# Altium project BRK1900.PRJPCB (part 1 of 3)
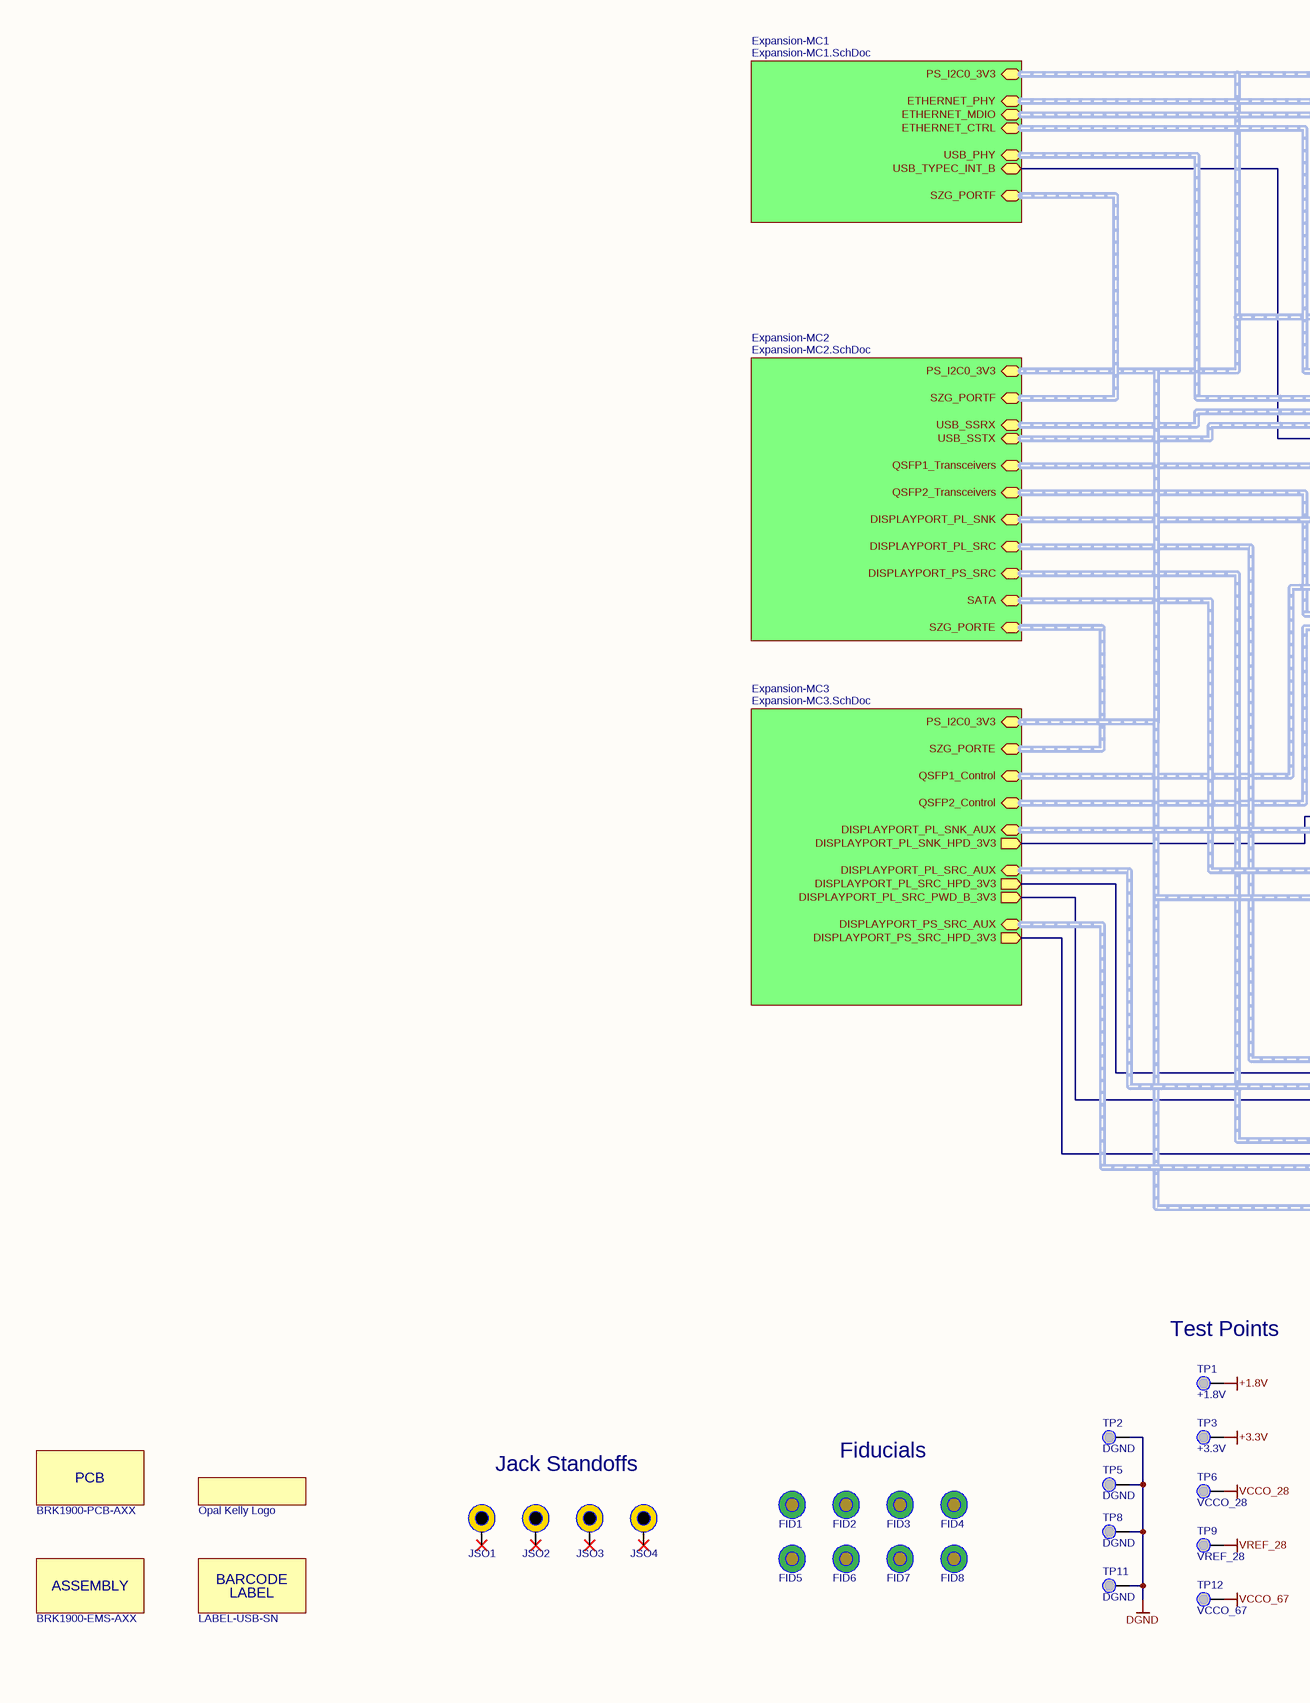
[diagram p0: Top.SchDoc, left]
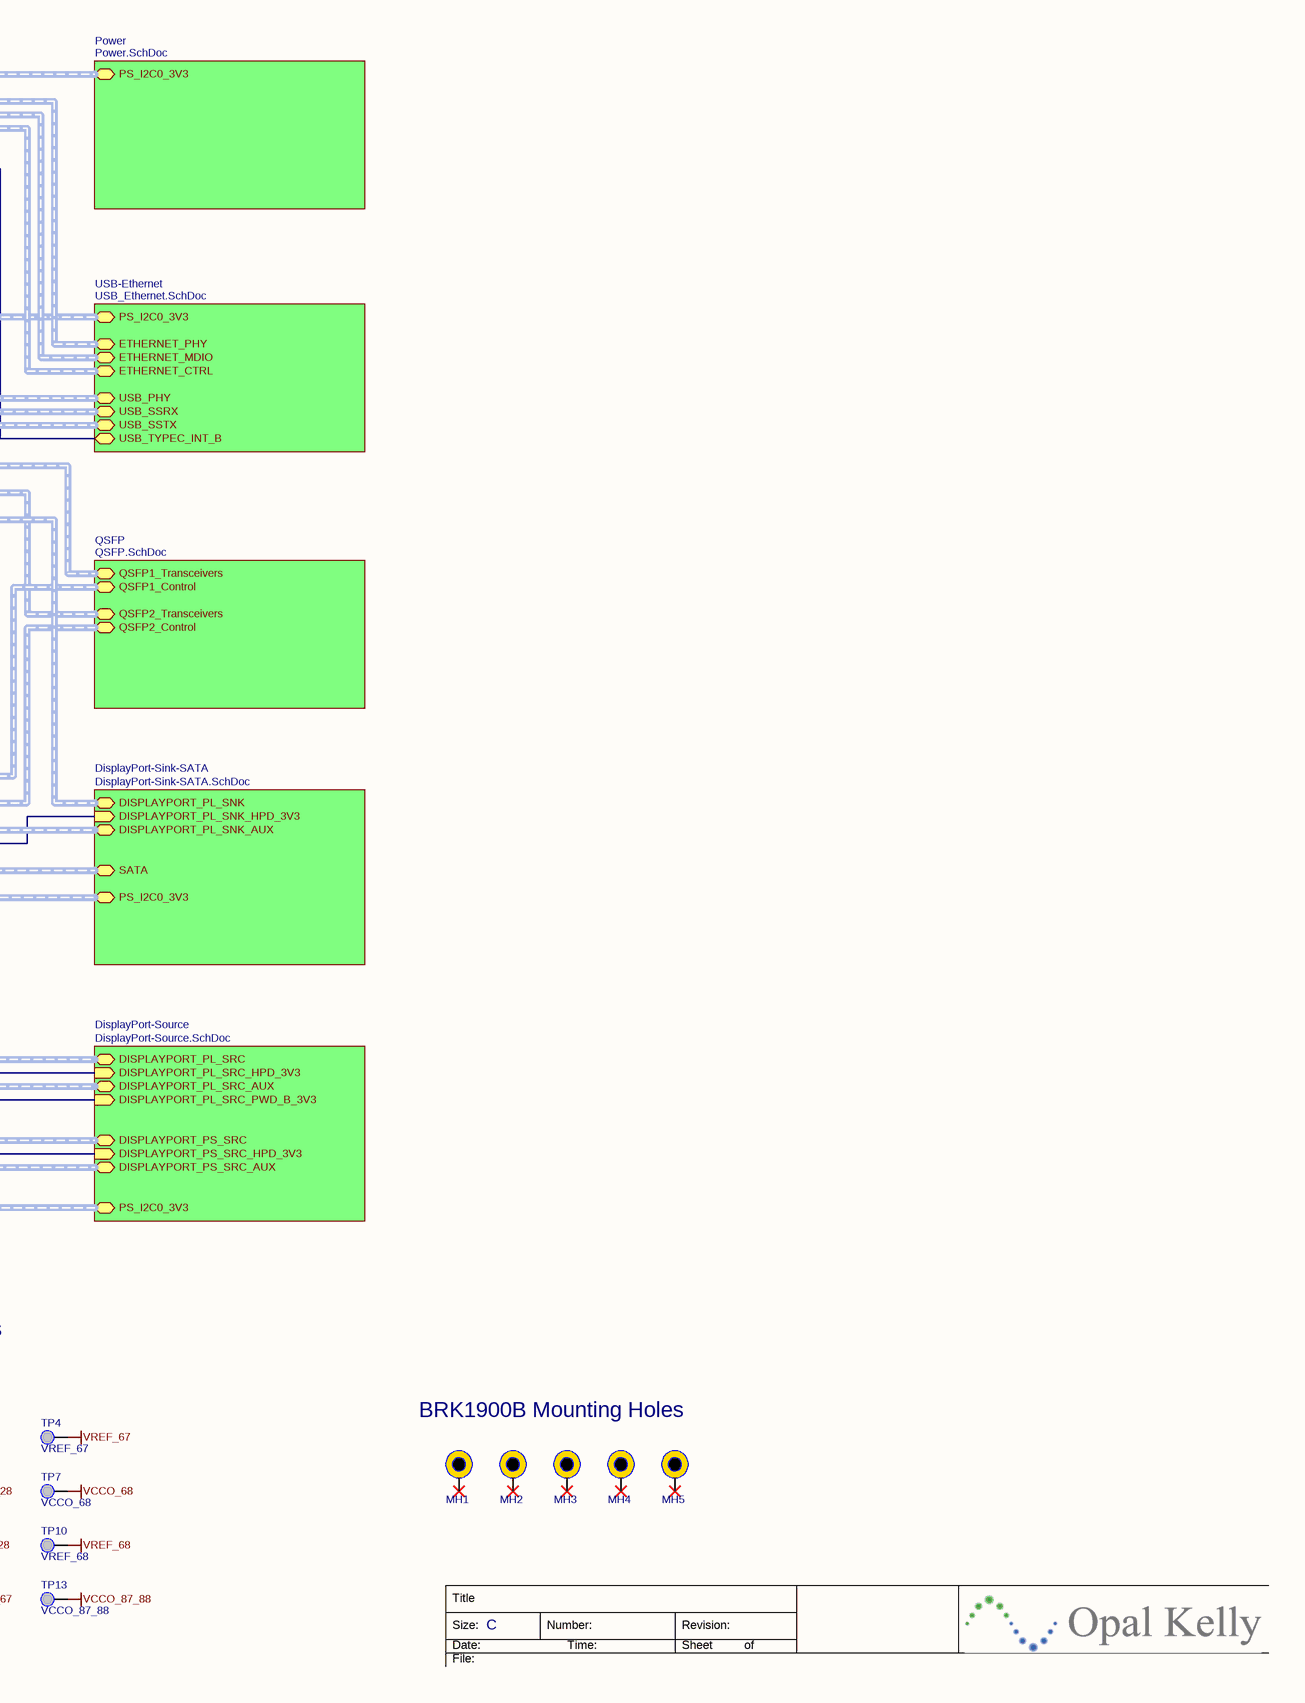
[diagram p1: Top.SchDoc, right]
BOM_Revision: 02; Part_Number: BRK1900; PCB_Revision: A; VariantBoms: 7CG=001863,7EV=001875,7EG=001889,11EG=001890
9 sheets, 514 parts. Net scope: hierarchical (ports join the sheet entries above them; power ports are global).
Board file: BRK1900.PcbDoc
Sheets:
  Top.SchDoc
    USB-Ethernet = USB_Ethernet.SchDoc
    QSFP = QSFP.SchDoc
    Expansion-MC1 = Expansion-MC1.SchDoc
    Expansion-MC2 = Expansion-MC2.SchDoc
    Expansion-MC3 = Expansion-MC3.SchDoc
    Power = Power.SchDoc
    DisplayPort-Sink-SATA = DisplayPort-Sink-SATA.SchDoc
    DisplayPort-Source = DisplayPort-Source.SchDoc

## Sheet Top.SchDoc: BRK1900 - Top Level
size C; Organization: Opal Kelly; Address1: 13500 SW 72nd Ave STE 100; Address3: Portland, OR  97223; Address4: http://www.opalkelly.com; DocumentNumber: xxx; Revision: 1; SheetNumber: 1; SheetTotal: 9; PageSetup: Record=PageOptions¦CenterHorizontal=True¦CenterVertical=True¦PrintScale=0.52¦XCorrection=1.00¦YCorrection=1.00¦PrintKind=0¦BorderSize=5000000¦LeftOffset=0¦BottomOffset=0¦Orientation=2¦PaperLength=1000¦PaperWidth=1000¦Scale=100¦PaperSource=15¦PrintQuality=600¦MediaType=1¦DitherType=10¦PaperKind=Letter¦PrintScaleMode=1

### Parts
*1  Opal Kelly Logo  [okLogo-23x5]
ASSY1  BRK1900-EMS-AXX  (mechanical)
FID1  FIDUCIAL  [FID1MM/2MM-SS]  (value not drawn)
FID2  FIDUCIAL  [FID1MM/2MM-SS]  (value not drawn)
FID3  FIDUCIAL  [FID1MM/2MM-SS]  (value not drawn)
FID4  FIDUCIAL  [FID1MM/2MM-SS]  (value not drawn)
FID5  FIDUCIAL  [FID1MM/2MM-SS]  (value not drawn)
FID6  FIDUCIAL  [FID1MM/2MM-SS]  (value not drawn)
FID7  FIDUCIAL  [FID1MM/2MM-SS]  (value not drawn)
FID8  FIDUCIAL  [FID1MM/2MM-SS]  (value not drawn)
JSO1  Jack Screw Standoff  [JSO-0515-01]  (value not drawn)
JSO2  Jack Screw Standoff  [JSO-0515-01]  (value not drawn)
JSO3  Jack Screw Standoff  [JSO-0515-01]  (value not drawn)
JSO4  Jack Screw Standoff  [JSO-0515-01]  (value not drawn)
LABEL1  LABEL-USB-SN  (mechanical)
MH1  MTG  [MTG-3.2/6.5-PTH]  (value not drawn)
MH2  MTG  [MTG-3.2/6.5-PTH]  (value not drawn)
MH3  MTG  [MTG-3.2/6.5-PTH]  (value not drawn)
MH4  MTG  [MTG-3.2/6.5-PTH]  (value not drawn)
MH5  MTG  [MTG-3.2/6.5-PTH]  (value not drawn)
PCB1  BRK1900-PCB-AXX  (mechanical)
TP1  +1.8V  [TP-PTH-25/45]
TP2  DGND  [TP-PTH-25/45]
TP3  +3.3V  [TP-PTH-25/45]
TP4  VREF_67  [TP-PTH-25/45]
TP5  DGND  [TP-PTH-25/45]
TP6  VCCO_28  [TP-PTH-25/45]
TP7  VCCO_68  [TP-PTH-25/45]
TP8  DGND  [TP-PTH-25/45]
TP9  VREF_28  [TP-PTH-25/45]
TP10  VREF_68  [TP-PTH-25/45]
TP11  DGND  [TP-PTH-25/45]
TP12  VCCO_67  [TP-PTH-25/45]
TP13  VCCO_87_88  [TP-PTH-25/45]

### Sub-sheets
DisplayPort-Sink-SATA = DisplayPort-Sink-SATA.SchDoc: DISPLAYPORT_PL_SNK (bidir, harness DISPLAYPORT), SATA (bidir, harness SATA), DISPLAYPORT_PL_SNK_HPD_3V3 (in), DISPLAYPORT_PL_SNK_AUX (bidir, harness DIFF_PAIR), PS_I2C0_3V3 (bidir, harness I2C)
DisplayPort-Source = DisplayPort-Source.SchDoc: DISPLAYPORT_PL_SRC_AUX (bidir, harness DIFF_PAIR), DISPLAYPORT_PS_SRC (bidir, harness DISPLAYPORT), DISPLAYPORT_PL_SRC_HPD_3V3 (in), DISPLAYPORT_PL_SRC (bidir, harness DISPLAYPORT), DISPLAYPORT_PS_SRC_AUX (bidir, harness DIFF_PAIR), DISPLAYPORT_PL_SRC_PWD_B_3V3 (in), DISPLAYPORT_PS_SRC_HPD_3V3 (in), PS_I2C0_3V3 (bidir, harness I2C)
Expansion-MC1 = Expansion-MC1.SchDoc: USB_PHY (bidir, harness USB_PHY), PS_I2C0_3V3 (bidir, harness I2C), SZG_PORTF (bidir, harness SYZYGY_TXR4), ETHERNET_PHY (bidir, harness ETH_PHY), USB_TYPEC_INT_B (bidir), ETHERNET_MDIO (bidir, harness ETH_MDIO), ETHERNET_CTRL (bidir, harness ETH_CTRL)
Expansion-MC2 = Expansion-MC2.SchDoc: USB_SSTX (bidir, harness DIFF_PAIR), SATA (bidir, harness SATA), USB_SSRX (bidir, harness DIFF_PAIR), QSFP1_Transceivers (bidir, harness QSFP_Transceivers), QSFP2_Transceivers (bidir, harness QSFP_Transceivers), SZG_PORTE (bidir, harness SYZYGY_TXR4), SZG_PORTF (bidir, harness SYZYGY_TXR4), PS_I2C0_3V3 (bidir, harness I2C), DISPLAYPORT_PL_SNK (bidir, harness DISPLAYPORT), DISPLAYPORT_PL_SRC (bidir, harness DISPLAYPORT), DISPLAYPORT_PS_SRC (bidir, harness DISPLAYPORT)
Expansion-MC3 = Expansion-MC3.SchDoc: QSFP1_Control (bidir, harness QSFP_Control), QSFP2_Control (bidir, harness QSFP_Control), SZG_PORTE (bidir, harness SYZYGY_TXR4), PS_I2C0_3V3 (bidir, harness I2C), DISPLAYPORT_PL_SNK_AUX (bidir, harness DIFF_PAIR), DISPLAYPORT_PL_SNK_HPD_3V3 (out), DISPLAYPORT_PL_SRC_AUX (bidir, harness DIFF_PAIR), DISPLAYPORT_PL_SRC_HPD_3V3 (out), DISPLAYPORT_PL_SRC_PWD_B_3V3 (out), DISPLAYPORT_PS_SRC_AUX (bidir, harness DIFF_PAIR), DISPLAYPORT_PS_SRC_HPD_3V3 (out)
Power = Power.SchDoc: PS_I2C0_3V3 (bidir, harness I2C)
QSFP = QSFP.SchDoc: QSFP1_Control (bidir, harness QSFP_Control), QSFP2_Control (bidir, harness QSFP_Control), QSFP1_Transceivers (bidir, harness QSFP_Transceivers), QSFP2_Transceivers (bidir, harness QSFP_Transceivers)
USB-Ethernet = USB_Ethernet.SchDoc: ETHERNET_PHY (bidir, harness ETH_PHY), USB_SSRX (bidir, harness DIFF_PAIR), USB_SSTX (bidir, harness DIFF_PAIR), PS_I2C0_3V3 (bidir, harness I2C), ETHERNET_MDIO (bidir, harness ETH_MDIO), ETHERNET_CTRL (bidir, harness ETH_CTRL), USB_PHY (bidir, harness USB_PHY), USB_TYPEC_INT_B (bidir)

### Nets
+1.8V: TP1.1(PIN)
+3.3V: TP3.1(PIN)
DGND: TP2.1(PIN) TP5.1(PIN) TP8.1(PIN) TP11.1(PIN)
VCCO_28: TP6.1(PIN)
VCCO_67: TP12.1(PIN)
VCCO_68: TP7.1(PIN)
VCCO_87_88: TP13.1(PIN)
VREF_28: TP9.1(PIN)
VREF_67: TP4.1(PIN)
VREF_68: TP10.1(PIN)
DISPLAYPORT_PL_SNK_HPD_3V3: sheet Expansion-MC3/DISPLAYPORT_PL_SNK_HPD_3V3, sheet DisplayPort-Sink-SATA/DISPLAYPORT_PL_SNK_HPD_3V3
DISPLAYPORT_PL_SRC_HPD_3V3: sheet Expansion-MC3/DISPLAYPORT_PL_SRC_HPD_3V3, sheet DisplayPort-Source/DISPLAYPORT_PL_SRC_HPD_3V3
DISPLAYPORT_PL_SRC_PWD_B_3V3: sheet Expansion-MC3/DISPLAYPORT_PL_SRC_PWD_B_3V3, sheet DisplayPort-Source/DISPLAYPORT_PL_SRC_PWD_B_3V3
DISPLAYPORT_PS_SRC_HPD_3V3: sheet Expansion-MC3/DISPLAYPORT_PS_SRC_HPD_3V3, sheet DisplayPort-Source/DISPLAYPORT_PS_SRC_HPD_3V3
USB_TYPEC_INT_B: sheet USB-Ethernet/USB_TYPEC_INT_B, sheet Expansion-MC1/USB_TYPEC_INT_B

Not connected (* = marked no-connect by the designer): JSO1 1*; JSO2 1*; JSO3 1*; JSO4 1*; MH1 1*; MH2 1*; MH3 1*; MH4 1*; MH5 1*

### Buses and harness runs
harness sheet DisplayPort-Sink-SATA/DISPLAYPORT_PL_SNK = sheet Expansion-MC2/DISPLAYPORT_PL_SNK
harness sheet DisplayPort-Sink-SATA/DISPLAYPORT_PL_SNK_AUX = sheet Expansion-MC3/DISPLAYPORT_PL_SNK_AUX
harness sheet DisplayPort-Sink-SATA/PS_I2C0_3V3 = sheet DisplayPort-Source/PS_I2C0_3V3 = sheet Expansion-MC1/PS_I2C0_3V3 = sheet Expansion-MC2/PS_I2C0_3V3 = sheet Expansion-MC3/PS_I2C0_3V3 = sheet Power/PS_I2C0_3V3 = sheet USB-Ethernet/PS_I2C0_3V3
harness sheet DisplayPort-Sink-SATA/SATA = sheet Expansion-MC2/SATA
harness sheet DisplayPort-Source/DISPLAYPORT_PL_SRC = sheet Expansion-MC2/DISPLAYPORT_PL_SRC
harness sheet DisplayPort-Source/DISPLAYPORT_PL_SRC_AUX = sheet Expansion-MC3/DISPLAYPORT_PL_SRC_AUX
harness sheet DisplayPort-Source/DISPLAYPORT_PS_SRC = sheet Expansion-MC2/DISPLAYPORT_PS_SRC
harness sheet DisplayPort-Source/DISPLAYPORT_PS_SRC_AUX = sheet Expansion-MC3/DISPLAYPORT_PS_SRC_AUX
harness sheet Expansion-MC1/ETHERNET_CTRL = sheet USB-Ethernet/ETHERNET_CTRL
harness sheet Expansion-MC1/ETHERNET_MDIO = sheet USB-Ethernet/ETHERNET_MDIO
harness sheet Expansion-MC1/ETHERNET_PHY = sheet USB-Ethernet/ETHERNET_PHY
harness sheet Expansion-MC1/SZG_PORTF = sheet Expansion-MC2/SZG_PORTF
harness sheet Expansion-MC1/USB_PHY = sheet USB-Ethernet/USB_PHY
harness sheet Expansion-MC2/QSFP1_Transceivers = sheet QSFP/QSFP1_Transceivers
harness sheet Expansion-MC2/QSFP2_Transceivers = sheet QSFP/QSFP2_Transceivers
harness sheet Expansion-MC2/SZG_PORTE = sheet Expansion-MC3/SZG_PORTE
harness sheet Expansion-MC2/USB_SSRX = sheet USB-Ethernet/USB_SSRX
harness sheet Expansion-MC2/USB_SSTX = sheet USB-Ethernet/USB_SSTX
harness sheet Expansion-MC3/QSFP1_Control = sheet QSFP/QSFP1_Control
harness sheet Expansion-MC3/QSFP2_Control = sheet QSFP/QSFP2_Control

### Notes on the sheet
- (near TP1) Test Points
- Fiducials
- BRK1900B Mounting Holes
- Jack Standoffs
- Title
- Size:
- Date:
- File:
- C
- Number:
- Time:
- Revision:
- Sheet
- of

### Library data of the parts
*1 = OKLOGO: partnumber: ALIGNI_IGNORE
ASSY1 = 001954: Assembly Service; Partnumber: 001954; manufacturer: PCB Assembly Cost; description: BRK1900 PCB assembly
FID1-FID8 = FIDUCIAL: PCB fiducial; partnumber: ALIGNI_IGNORE
JSO1-JSO4 = 001879: Jack screw standoff, 5mm board stack height; Partnumber: 001879; manufacturer: Samtec
LABEL1 = 000605: Barcode serial number labels for USB devices; Manufacturer: Techiant; partnumber: 000605
MH1-MH5 = MTG: Mounting hole; partnumber: ALIGNI_IGNORE
PCB1 = 001953: PCB; Partnumber: 001953; manufacturer: Jiangmen Suntak Circuit Technology; description: PCB for BRK1900
TP1-TP13 = TP-PTH-25/45: Test point, plated through-hole, 25/45mil; partnumber: ALIGNI_IGNORE

## Sheet USB_Ethernet.SchDoc: BRK1900 - USB, Ethernet
size C; Organization: Opal Kelly; Address1: 13500 SW 72nd Ave STE 100; Address2: Portland, OR  97223; Address3: 217.391.3724; Address4: http://www.opalkelly.com; DocumentNumber: xxx; Revision: 1; SheetNumber: 8; SheetTotal: 9; PageSetup: Record=PageOptions¦CenterHorizontal=True¦CenterVertical=True¦PrintScale=0.52¦XCorrection=1.00¦YCorrection=1.00¦PrintKind=0¦BorderSize=5000000¦LeftOffset=0¦BottomOffset=0¦Orientation=2¦PaperLength=1000¦PaperWidth=1000¦Scale=100¦PaperSource=7¦PrintQuality=-4¦MediaType=1¦DitherType=10¦PaperKind=Letter¦PrintScaleMode=1
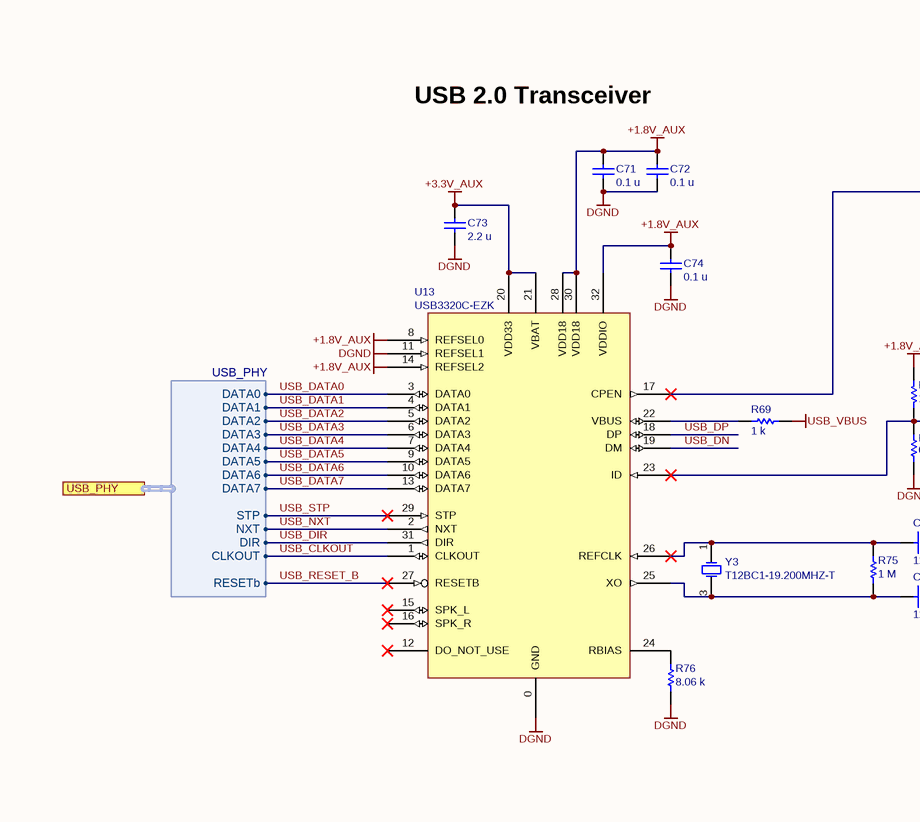
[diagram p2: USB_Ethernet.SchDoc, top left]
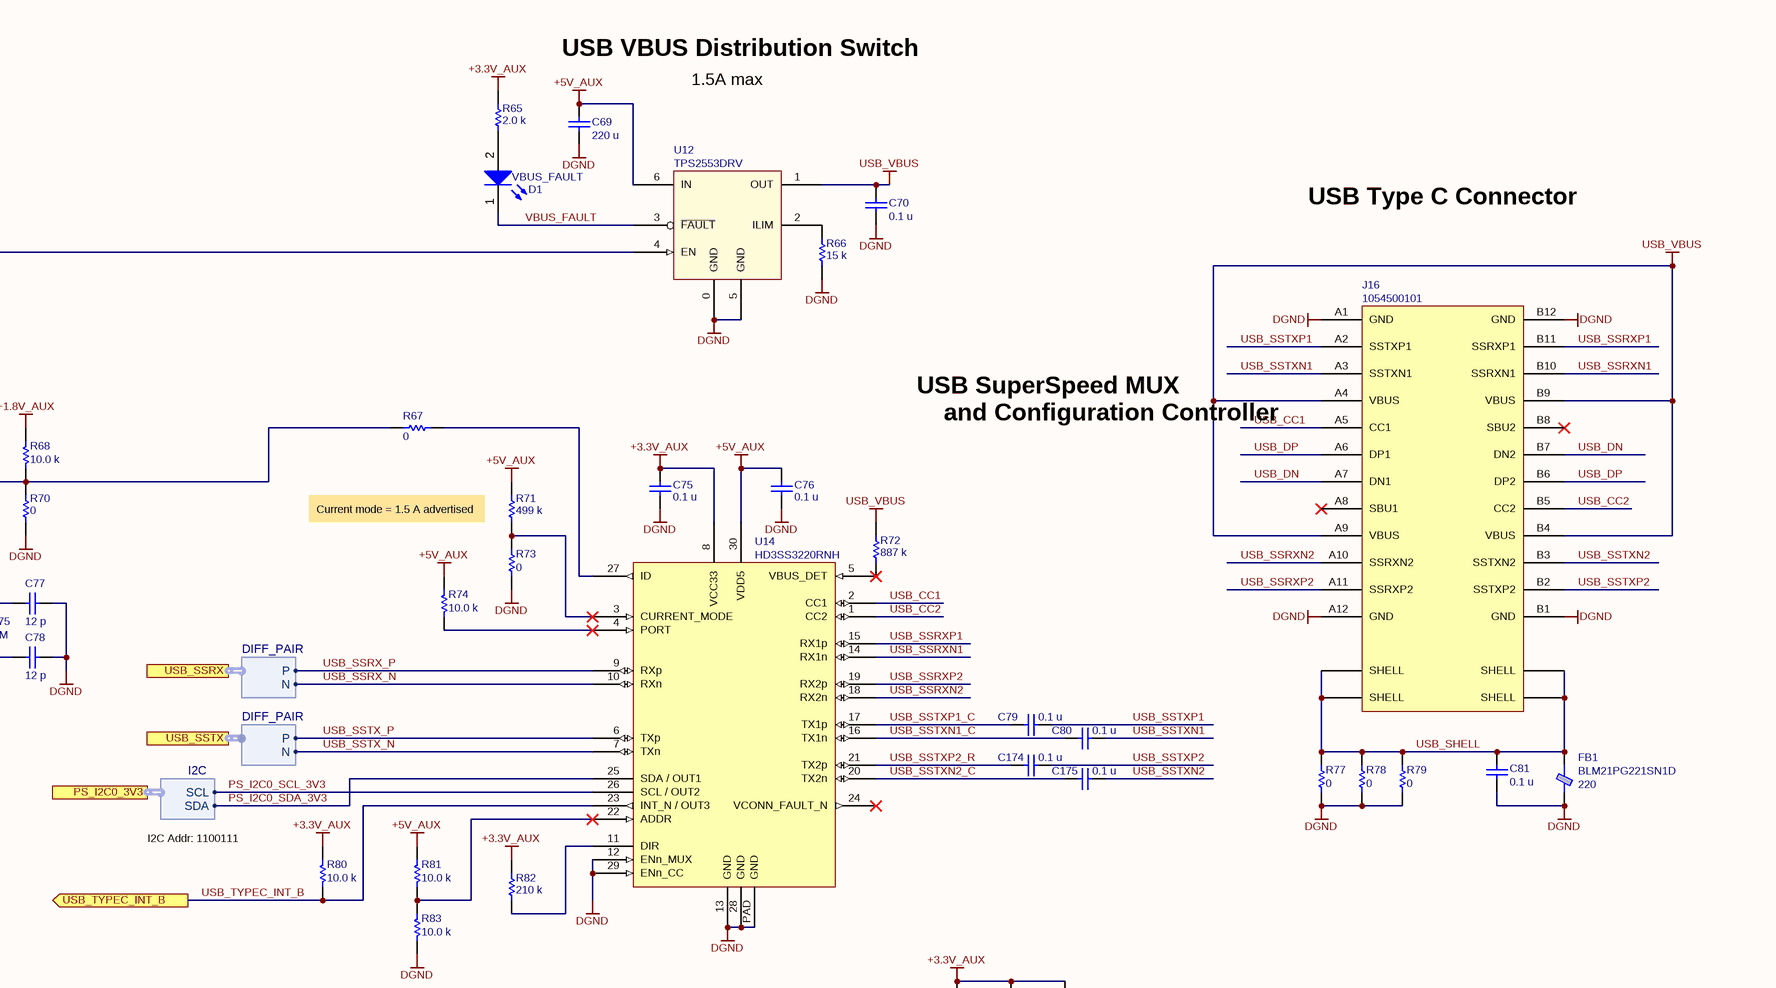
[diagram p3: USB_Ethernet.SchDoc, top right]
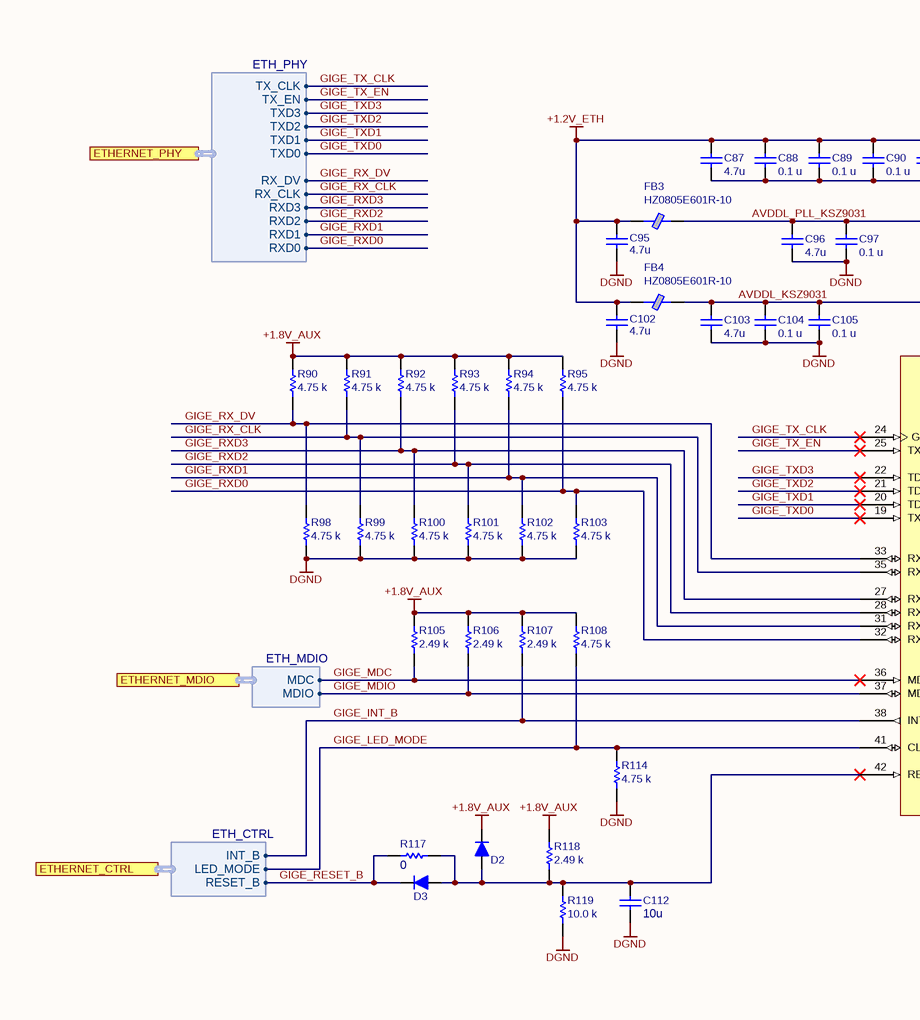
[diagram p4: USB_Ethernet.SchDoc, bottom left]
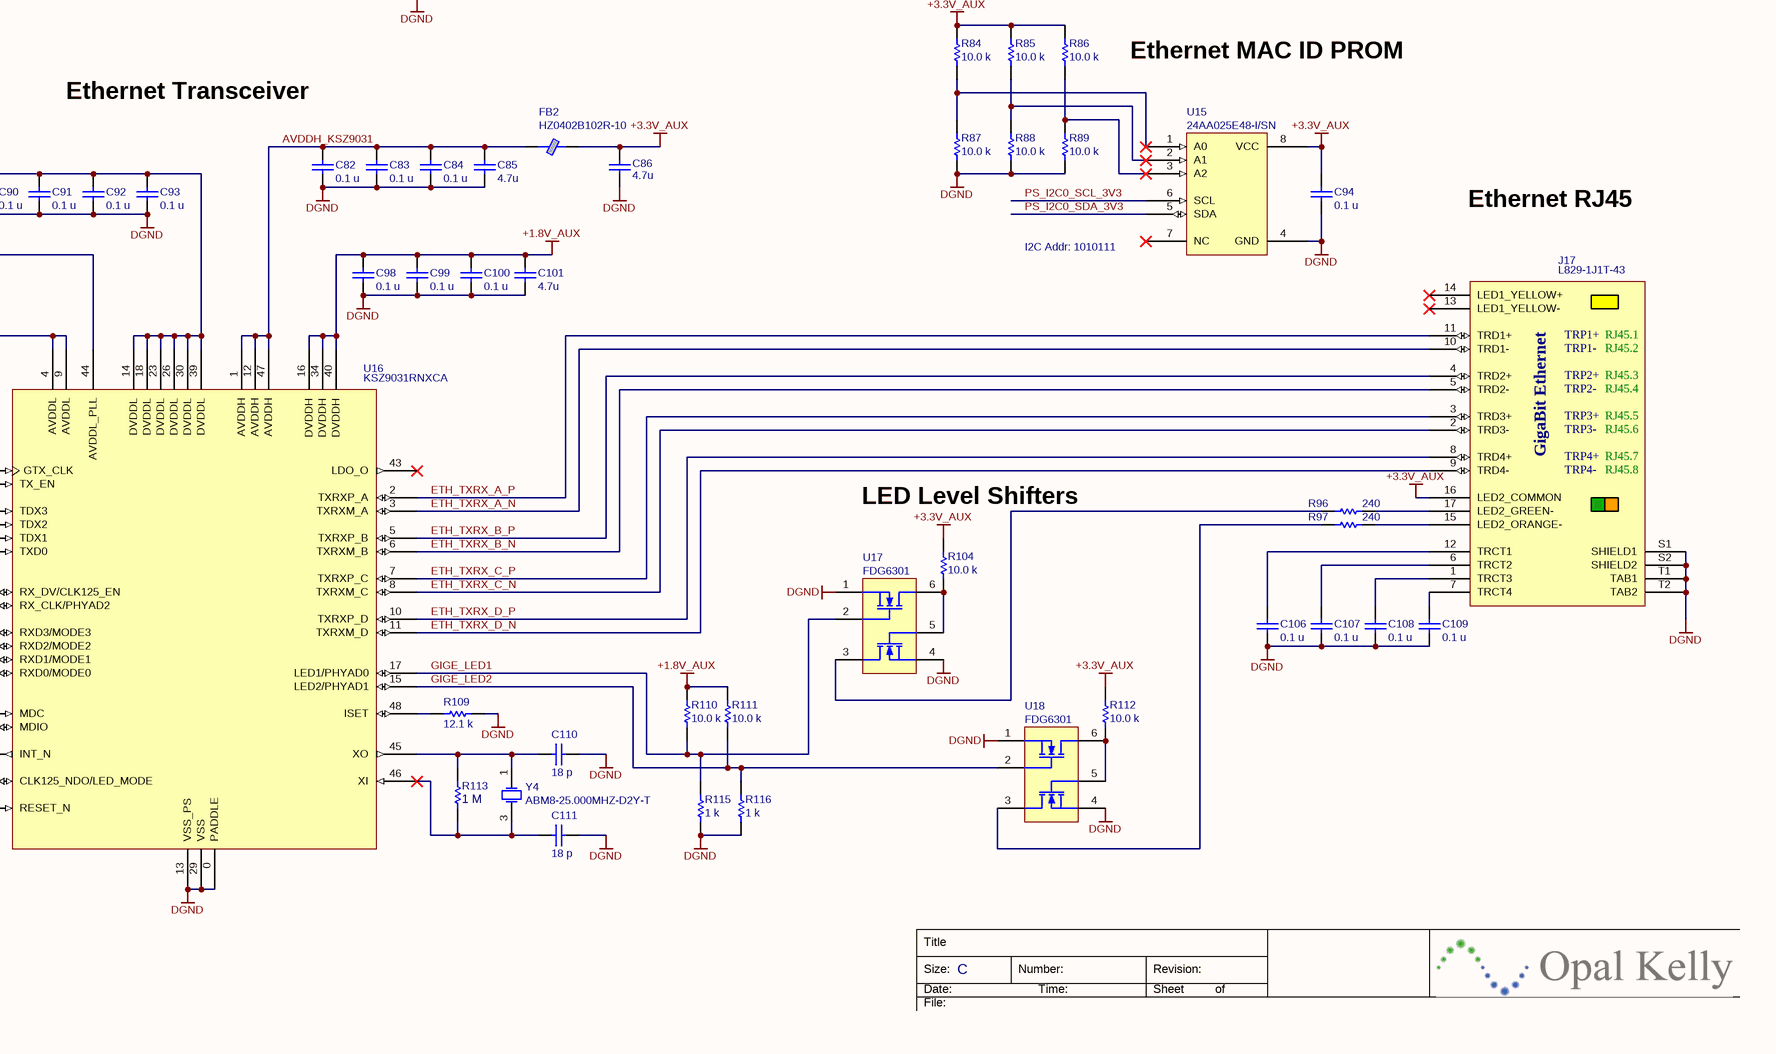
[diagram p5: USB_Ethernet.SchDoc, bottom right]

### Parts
C69  value 220 u  [CAPC3225N]  (hidden comment: JMK325ABJ227MM-T)
C70  value 0.1 u  [CAPC1005X06A]  (hidden comment: C0402C104K8PACTU)
C71  value 0.1 u  [CAPC1005X06A]  (hidden comment: C0402C104K8PACTU)
C72  value 0.1 u  [CAPC1005X06A]  (hidden comment: C0402C104K8PACTU)
C73  value 2.2 u  [CAPC1005X06A]  (hidden comment: JMK105BJ225MV-F)
C74  value 0.1 u  [CAPC1005X06A]  (hidden comment: C0402C104K8PACTU)
C75  value 0.1 u  [CAPC1005X06A]  (hidden comment: C0402C104K8PACTU)
C76  value 0.1 u  [CAPC1005X06A]  (hidden comment: C0402C104K8PACTU)
C77  value 12 p  [CAPC1005X06A]  (hidden comment: C0402C120J5GACTU)
C78  value 12 p  [CAPC1005X06A]  (hidden comment: C0402C120J5GACTU)
C79  value 0.1 u  [CAPC1005X06A]  (hidden comment: C0402C104K8PACTU)
C80  value 0.1 u  [CAPC1005X06A]  (hidden comment: C0402C104K8PACTU)
C81  value 0.1 u  [CAPC1005X06A]  (hidden comment: C0402C104K8PACTU)
C82  value 0.1 u  [CAPC1005X06A]  (hidden comment: C0402C104K8PACTU)
C83  value 0.1 u  [CAPC1005X06A]  (hidden comment: C0402C104K8PACTU)
C84  value 0.1 u  [CAPC1005X06A]  (hidden comment: C0402C104K8PACTU)
C85  value 4.7u  [CAPC1005X06A]  (hidden comment: JMK105BBJ475MV-F)
C86  value 4.7u  [CAPC1005X06A]  (hidden comment: JMK105BBJ475MV-F)
C87  value 4.7u  [CAPC1005X06A]  (hidden comment: JMK105BBJ475MV-F)
C88  value 0.1 u  [CAPC1005X06A]  (hidden comment: C0402C104K8PACTU)
C89  value 0.1 u  [CAPC1005X06A]  (hidden comment: C0402C104K8PACTU)
C90  value 0.1 u  [CAPC1005X06A]  (hidden comment: C0402C104K8PACTU)
C91  value 0.1 u  [CAPC1005X06A]  (hidden comment: C0402C104K8PACTU)
C92  value 0.1 u  [CAPC1005X06A]  (hidden comment: C0402C104K8PACTU)
C93  value 0.1 u  [CAPC1005X06A]  (hidden comment: C0402C104K8PACTU)
C94  value 0.1 u  [CAPC1005X06A]  (hidden comment: C0402C104K8PACTU)
C95  value 4.7u  [CAPC1005X06A]  (hidden comment: JMK105BBJ475MV-F)
C96  value 4.7u  [CAPC1005X06A]  (hidden comment: JMK105BBJ475MV-F)
C97  value 0.1 u  [CAPC1005X06A]  (hidden comment: C0402C104K8PACTU)
C98  value 0.1 u  [CAPC1005X06A]  (hidden comment: C0402C104K8PACTU)
C99  value 0.1 u  [CAPC1005X06A]  (hidden comment: C0402C104K8PACTU)
C100  value 0.1 u  [CAPC1005X06A]  (hidden comment: C0402C104K8PACTU)
C101  value 4.7u  [CAPC1005X06A]  (hidden comment: JMK105BBJ475MV-F)
C102  value 4.7u  [CAPC1005X06A]  (hidden comment: JMK105BBJ475MV-F)
C103  value 4.7u  [CAPC1005X06A]  (hidden comment: JMK105BBJ475MV-F)
C104  value 0.1 u  [CAPC1005X06A]  (hidden comment: C0402C104K8PACTU)
C105  value 0.1 u  [CAPC1005X06A]  (hidden comment: C0402C104K8PACTU)
C106  value 0.1 u  [CAPC1005X06A]  (hidden comment: C0402C104K8PACTU)
C107  value 0.1 u  [CAPC1005X06A]  (hidden comment: C0402C104K8PACTU)
C108  value 0.1 u  [CAPC1005X06A]  (hidden comment: C0402C104K8PACTU)
C109  value 0.1 u  [CAPC1005X06A]  (hidden comment: C0402C104K8PACTU)
C110  value 18 p  [CAPC1005X06A]  (hidden comment: C0402C180J5GACTU)
C111  value 18 p  [CAPC1005X06A]  (hidden comment: C0402C180J5GACTU)
C112  value 10u  [CAPC2012X14N]  (hidden comment: LMK212BJ106KG-T)
C174  value 0.1 u  [CAPC1005X06A]  (hidden comment: C0402C104K8PACTU)
C175  value 0.1 u  [CAPC1005X06A]  (hidden comment: C0402C104K8PACTU)
D1  VBUS_FAULT  [CD1608-0603-PIN1-CATHODE]
D2  Diode  [SOD-123]  (value not drawn)
D3  Diode  [SOD-123]  (value not drawn)
FB1  BLM21PG221SN1D  value 220  [RESC2012N]
FB2  HZ0402B102R-10  [INDC1005X05N]
FB3  HZ0805E601R-10  [RESC2012N]
FB4  HZ0805E601R-10  [RESC2012N]
J16  1054500101  [1054500101]
J17  L829-1J1T-43  [L829-1J1T-43]
R65  value 2.0 k  [RESC1005X06A]  (hidden comment: CRCW04022K00FKED)
R66  value 15 k  [RESC1005X06A]  (hidden comment: CRCW040215K0FKED)
R67  value 0  [RESC1005X06A]  (hidden comment: CRCW04020000Z0ED)
R68  value 10.0 k  [RESC1005X06A]  (hidden comment: CRCW040210K0FKED)
R69  value 1 k  [RESC1005X06A]  (hidden comment: CRCW04021K00FKED)
R70  value 0  [RESC1005X06A]  (hidden comment: CRCW04020000Z0ED)
R71  value 499 k  [RESC1005X06A]  (hidden comment: CRCW0402499KFKEDC)
R72  value 887 k  [RESC1005X06A]  (hidden comment: CRCW0402887KFKED)
R73  value 0  [RESC1005X06A]  (hidden comment: CRCW04020000Z0ED)
R74  value 10.0 k  [RESC1005X06A]  (hidden comment: CRCW040210K0FKED)
R75  value 1 M  [RESC1005X06A]  (hidden comment: CRCW04021M00JNED)
R76  value 8.06 k  [RESC1005X06A]  (hidden comment: CRCW04028K06FKED)
R77  value 0  [RESC1005X06A]  (hidden comment: CRCW04020000Z0ED)
R78  value 0  [RESC1005X06A]  (hidden comment: CRCW04020000Z0ED)
R79  value 0  [RESC1005X06A]  (hidden comment: CRCW04020000Z0ED)
R80  value 10.0 k  [RESC1005X06A]  (hidden comment: CRCW040210K0FKED)
R81  value 10.0 k  [RESC1005X06A]  (hidden comment: CRCW040210K0FKED)
R82  value 210 k  [RESC1005X06A]  (hidden comment: CRCW0402210KFKED)
R83  value 10.0 k  [RESC1005X06A]  (hidden comment: CRCW040210K0FKED)
R84  value 10.0 k  [RESC1005X06A]  (hidden comment: CRCW040210K0FKED)
R85  value 10.0 k  [RESC1005X06A]  (hidden comment: CRCW040210K0FKED)
R86  value 10.0 k  [RESC1005X06A]  (hidden comment: CRCW040210K0FKED)
R87  value 10.0 k  [RESC1005X06A]  (hidden comment: CRCW040210K0FKED)
R88  value 10.0 k  [RESC1005X06A]  (hidden comment: CRCW040210K0FKED)
R89  value 10.0 k  [RESC1005X06A]  (hidden comment: CRCW040210K0FKED)
R90  value 4.75 k  [RESC1005X06A]  (hidden comment: CRCW04024K75FKED)
R91  value 4.75 k  [RESC1005X06A]  (hidden comment: CRCW04024K75FKED)
R92  value 4.75 k  [RESC1005X06A]  (hidden comment: CRCW04024K75FKED)
R93  value 4.75 k  [RESC1005X06A]  (hidden comment: CRCW04024K75FKED)
R94  value 4.75 k  [RESC1005X06A]  (hidden comment: CRCW04024K75FKED)
R95  value 4.75 k  [RESC1005X06A]  (hidden comment: CRCW04024K75FKED)
R96  value 240  [RESC1005X06A]  (hidden comment: CRCW0402240RFKED)
R97  value 240  [RESC1005X06A]  (hidden comment: CRCW0402240RFKED)
R98  value 4.75 k  [RESC1005X06A]  (hidden comment: CRCW04024K75FKED)
R99  value 4.75 k  [RESC1005X06A]  (hidden comment: CRCW04024K75FKED)
R100  value 4.75 k  [RESC1005X06A]  (hidden comment: CRCW04024K75FKED)
R101  value 4.75 k  [RESC1005X06A]  (hidden comment: CRCW04024K75FKED)
R102  value 4.75 k  [RESC1005X06A]  (hidden comment: CRCW04024K75FKED)
R103  value 4.75 k  [RESC1005X06A]  (hidden comment: CRCW04024K75FKED)
R104  value 10.0 k  [RESC1005X06A]  (hidden comment: CRCW040210K0FKED)
R105  value 2.49 k  [RESC1005X06A]  (hidden comment: CRCW04022K49FKED)
R106  value 2.49 k  [RESC1005X06A]  (hidden comment: CRCW04022K49FKED)
R107  value 2.49 k  [RESC1005X06A]  (hidden comment: CRCW04022K49FKED)
R108  value 4.75 k  [RESC1005X06A]  (hidden comment: CRCW04024K75FKED)
R109  value 12.1 k  [RESC1005X06A]  (hidden comment: CRCW040212K1FKED)
R110  value 10.0 k  [RESC1005X06A]  (hidden comment: CRCW040210K0FKED)
R111  value 10.0 k  [RESC1005X06A]  (hidden comment: CRCW040210K0FKED)
R112  value 10.0 k  [RESC1005X06A]  (hidden comment: CRCW040210K0FKED)
R113  value 1 M  [RESC1005X06A]  (hidden comment: CRCW04021M00JNED)
R114  value 4.75 k  [RESC1005X06A]  (hidden comment: CRCW04024K75FKED)
R115  value 1 k  [RESC1005X06A]  (hidden comment: CRCW04021K00FKED)
R116  value 1 k  [RESC1005X06A]  (hidden comment: CRCW04021K00FKED)
R117  value 0  [RESC1005X06A]  (hidden comment: CRCW04020000Z0ED)
R118  value 2.49 k  [RESC1005X06A]  (hidden comment: CRCW04022K49FKED)
R119  value 10.0 k  [RESC1005X06A]  (hidden comment: CRCW040210K0FKED)
U12  TPS2553DRV  [S-PWSON-N6]
U13  USB3320C-EZK  [QFN-32]
U14  HD3SS3220RNH  [WQFN-30]
U15  24AA025E48-I/SN  [SO-G8]
U16  KSZ9031RNXCA  [QFN-48]
U17  FDG6301  [SOT363-6N]
U18  FDG6301  [SOT363-6N]
Y3  T12BC1-19.200MHZ-T  [OSC_SMD_32x25]
Y4  ABM8-25.000MHZ-D2Y-T  [OSC_SMD_32x25]

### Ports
ETHERNET_CTRL (harness ETH_CTRL), ETHERNET_MDIO (harness ETH_MDIO), ETHERNET_PHY (harness ETH_PHY), PS_I2C0_3V3 (harness I2C), USB_PHY (harness USB_PHY), USB_SSRX (harness DIFF_PAIR), USB_SSTX (harness DIFF_PAIR), USB_TYPEC_INT_B (out)

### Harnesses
USB_PHY: DATA0, DATA1, DATA2, DATA3, DATA4, DATA5, DATA6, DATA7, STP, NXT, DIR, CLKOUT, RESETb
I2C: SCL, SDA
ETH_PHY: TX_CLK, TX_EN, TXD3, TXD2, TXD1, TXD0, RX_DV, RX_CLK, RXD3, RXD2, RXD1, RXD0
ETH_CTRL: INT_B, LED_MODE, RESET_B
ETH_MDIO: MDC, MDIO
DIFF_PAIR: P, N

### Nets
+1.2V_ETH: C87.1 C88.2 C89.2 C90.2 C91.2 C92.2 C93.2 C95.2 C102.2 FB3.1 FB4.1 U16.14(DVDDL) U16.18(DVDDL) U16.23(DVDDL) U16.26(DVDDL) U16.30(DVDDL) U16.39(DVDDL)
+1.8V_AUX: C71.2 C72.2 C74.2 C98.2 C99.2 C100.2 C101.1 D2.2(K) R68.2 R90.2 R91.2 R92.2 R93.2 R94.2 R95.2 R105.2 R106.2 R107.2 R108.2 R110.2 R111.2 R118.2 U13.8(REFSEL0) U13.14(REFSEL2) U13.28(VDD18) U13.30(VDD18) U13.32(VDDIO) U16.16(DVDDH) U16.34(DVDDH) U16.40(DVDDH)
+3.3V_AUX: C73.2 C75.2 C86.2 C94.2 FB2.2 J17.16(LED2_COMMON) R65.2 R80.2 R82.2 R84.2 R85.2 R86.2 R104.2 R112.2 U13.20(VDD33) U13.21(VBAT) U14.8(VCC33) U15.8(VCC)
+5V_AUX: C69.2 C76.2 R71.2 R74.2 R81.2 U12.6(IN) U14.30(VDD5)
DGND: C69.1 C70.1 C71.1 C72.1 C73.1 C74.1 C75.1 C76.1 C77.1 C78.1 C81.1 C82.1 C83.1 C84.1 C85.2 C86.1 C87.2 C88.1 C89.1 C90.1 C91.1 C92.1 C93.1 C94.1 C95.1 C96.2 C97.1 C98.1 C99.1 C100.1 C101.2 C102.1 C103.2 C104.1 C105.1 C106.1 C107.1 C108.1 C109.1 C110.2 C111.2 C112.1 FB1.2 J16.A1(GND) J16.A12(GND) J16.B1(GND) J16.B12(GND) J17.S1(SHIELD1) J17.S2(SHIELD2) J17.T1(TAB1) J17.T2(TAB2) R66.1 R70.2 R73.2 R76.1 R77.2 R78.2 R79.2 R83.1 R87.1 R88.1 R89.1 R98.1 R99.1 R100.1 R101.1 R102.1 R103.1 R109.2 R114.1 R115.1 R116.1 R119.1 U12.0(GND) U12.5(GND) U13.0(GND) U13.11(REFSEL1) U14.12(ENn_MUX) U14.13(GND) U14.28(GND) U14.29(ENn_CC) U14.PAD(GND) U15.4(GND) U16.0(PADDLE) U16.13(VSS_PS) U16.29(VSS) U17.1(S1) U17.4(S2) U18.1(S1) U18.4(S2)
USB_VBUS: C70.2 J16.A4(VBUS) J16.A9(VBUS) J16.B4(VBUS) J16.B9(VBUS) R69.1 R72.2 U12.1(OUT)
AVDDH_KSZ9031: C82.2 C83.2 C84.2 C85.1 FB2.1 U16.1(AVDDH) U16.12(AVDDH) U16.47(AVDDH)
AVDDL_KSZ9031: C103.1 C104.2 C105.2 FB4.2 U16.4(AVDDL) U16.9(AVDDL)
AVDDL_PLL_KSZ9031: C96.1 C97.2 FB3.2 U16.44(AVDDL_PLL)
ETH_TXRX_A_N: J17.10(TRD1-) U16.3(TXRXM_A)
ETH_TXRX_A_P: J17.11(TRD1+) U16.2(TXRXP_A)
ETH_TXRX_B_N: J17.5(TRD2-) U16.6(TXRXM_B)
ETH_TXRX_B_P: J17.4(TRD2+) U16.5(TXRXP_B)
ETH_TXRX_C_N: J17.2(TRD3-) U16.8(TXRXM_C)
ETH_TXRX_C_P: J17.3(TRD3+) U16.7(TXRXP_C)
ETH_TXRX_D_N: J17.9(TRD4-) U16.11(TXRXM_D)
ETH_TXRX_D_P: J17.8(TRD4+) U16.10(TXRXP_D)
GIGE_INT_B: R107.1 U16.38(INT_N) ; port ETHERNET_CTRL.INT_B
GIGE_LED1: R110.1 R115.2 U16.17(LED1/PHYAD0) U17.2(G1)
GIGE_LED2: R111.1 R116.2 U16.15(LED2/PHYAD1) U18.2(G1)
GIGE_LED_MODE: R108.1 R114.2 U16.41(CLK125_NDO/LED_MODE) ; port ETHERNET_CTRL.LED_MODE
GIGE_MDC: R105.1 U16.36(MDC) ; port ETHERNET_MDIO.MDC
GIGE_MDIO: R106.1 U16.37(MDIO) ; port ETHERNET_MDIO.MDIO
GIGE_RESET_B: D3.2(K) R117.1 ; port ETHERNET_CTRL.RESET_B
GIGE_RX_CLK: R91.1 R99.2 U16.35(RX_CLK/PHYAD2) ; port ETHERNET_PHY.RX_CLK
GIGE_RX_DV: R90.1 R98.2 U16.33(RX_DV/CLK125_EN) ; port ETHERNET_PHY.RX_DV
GIGE_RXD0: R95.1 R103.2 U16.32(RXD0/MODE0) ; port ETHERNET_PHY.RXD0
GIGE_RXD1: R94.1 R102.2 U16.31(RXD1/MODE1) ; port ETHERNET_PHY.RXD1
GIGE_RXD2: R93.1 R101.2 U16.28(RXD2/MODE2) ; port ETHERNET_PHY.RXD2
GIGE_RXD3: R92.1 R100.2 U16.27(RXD3/MODE3) ; port ETHERNET_PHY.RXD3
GIGE_TX_CLK: U16.24(GTX_CLK) ; port ETHERNET_PHY.TX_CLK
GIGE_TX_EN: U16.25(TX_EN) ; port ETHERNET_PHY.TX_EN
GIGE_TXD0: U16.19(TXD0) ; port ETHERNET_PHY.TXD0
GIGE_TXD1: U16.20(TDX1) ; port ETHERNET_PHY.TXD1
GIGE_TXD2: U16.21(TDX2) ; port ETHERNET_PHY.TXD2
GIGE_TXD3: U16.22(TDX3) ; port ETHERNET_PHY.TXD3
PS_I2C0_SCL_3V3: U14.26(SCL_/_OUT2) U15.6(SCL) ; port PS_I2C0_3V3.SCL
PS_I2C0_SDA_3V3: U14.25(SDA_/_OUT1) U15.5(SDA) ; port PS_I2C0_3V3.SDA
USB_CC1: J16.A5(CC1) U14.2(CC1)
USB_CC2: J16.B5(CC2) U14.1(CC2)
USB_CLKOUT: U13.1(CLKOUT) ; port USB_PHY.CLKOUT
USB_DATA0: U13.3(DATA0) ; port USB_PHY.DATA0
USB_DATA1: U13.4(DATA1) ; port USB_PHY.DATA1
USB_DATA2: U13.5(DATA2) ; port USB_PHY.DATA2
USB_DATA3: U13.6(DATA3) ; port USB_PHY.DATA3
USB_DATA4: U13.7(DATA4) ; port USB_PHY.DATA4
USB_DATA5: U13.9(DATA5) ; port USB_PHY.DATA5
USB_DATA6: U13.10(DATA6) ; port USB_PHY.DATA6
USB_DATA7: U13.13(DATA7) ; port USB_PHY.DATA7
USB_DIR: U13.31(DIR) ; port USB_PHY.DIR
USB_DN: J16.A7(DN1) J16.B7(DN2) U13.19(DM)
USB_DP: J16.A6(DP1) J16.B6(DP2) U13.18(DP)
USB_NXT: U13.2(NXT) ; port USB_PHY.NXT
USB_RESET_B: U13.27(RESETB) ; port USB_PHY.RESETb
USB_SHELL: C81.2 FB1.1 J16.M1(SHELL) J16.M2(SHELL) J16.M3(SHELL) J16.M4(SHELL) R77.1 R78.1 R79.1
USB_SSRX_N: U14.10(RXn) ; port USB_SSRX.N
USB_SSRX_P: U14.9(RXp) ; port USB_SSRX.P
USB_SSRXN1: J16.B10(SSRXN1) U14.14(RX1n)
USB_SSRXN2: J16.A10(SSRXN2) U14.18(RX2n)
USB_SSRXP1: J16.B11(SSRXP1) U14.15(RX1p)
USB_SSRXP2: J16.A11(SSRXP2) U14.19(RX2p)
USB_SSTX_N: U14.7(TXn) ; port USB_SSTX.N
USB_SSTX_P: U14.6(TXp) ; port USB_SSTX.P
USB_SSTXN1: C80.2 J16.A3(SSTXN1)
USB_SSTXN1_C: C80.1 U14.16(TX1n)
USB_SSTXN2: C175.2 J16.B3(SSTXN2)
USB_SSTXN2_C: C175.1 U14.20(TX2n)
USB_SSTXP1: C79.2 J16.A2(SSTXP1)
USB_SSTXP1_C: C79.1 U14.17(TX1p)
USB_SSTXP2: C174.2 J16.B2(SSTXP2)
USB_SSTXP2_R: C174.1 U14.21(TX2p)
USB_STP: U13.29(STP) ; port USB_PHY.STP
USB_TYPEC_INT_B: R80.1 U14.23(INT_N_/_OUT3) ; port USB_TYPEC_INT_B
VBUS_FAULT: D1.1(K) U12.3(~{FAULT})
NetC77_2: C77.2 R75.2 U13.26(REFCLK) Y3.1(OSC1)
NetC78_2: C78.2 R75.1 U13.25(XO) Y3.3(OSC2)
NetC106_2: C106.2 J17.12(TRCT1)
NetC107_2: C107.2 J17.6(TRCT2)
NetC108_2: C108.2 J17.1(TRCT3)
NetC109_2: C109.2 J17.7(TRCT4)
NetC110_1: C110.1 R113.2 U16.45(XO) Y4.1(OSC1)
NetC111_1: C111.1 R113.1 U16.46(XI) Y4.3(OSC2)
NetC112_2: C112.2 D2.1(A) D3.1(A) R117.2 R118.1 R119.2 U16.42(RESET_N)
NetD1_2: D1.2(A) R65.1
NetJ17_15: J17.15(LED2_ORANGE-) R97.1
NetJ17_17: J17.17(LED2_GREEN-) R96.1
NetR66_2: R66.2 U12.2(ILIM)
NetR67_1: R67.1 R68.1 R70.1 U13.23(ID)
NetR67_2: R67.2 U14.27(ID)
NetR69_2: R69.2 U13.22(VBUS)
NetR71_1: R71.1 R73.1 U14.3(CURRENT_MODE)
NetR72_1: R72.1 U14.5(VBUS_DET)
NetR74_1: R74.1 U14.4(PORT)
NetR76_2: R76.2 U13.24(RBIAS)
NetR81_1: R81.1 R83.2 U14.22(ADDR)
NetR82_1: R82.1 U14.11(DIR)
NetR84_1: R84.1 R87.2 U15.1(A0)
NetR85_1: R85.1 R88.2 U15.2(A1)
NetR86_1: R86.1 R89.2 U15.3(A2)
NetR96_2: R96.2 U17.3(D2)
NetR97_2: R97.2 U18.3(D2)
NetR104_1: R104.1 U17.5(G2) U17.6(D1)
NetR109_1: R109.1 U16.48(ISET)
NetR112_1: R112.1 U18.5(G2) U18.6(D1)
NetU12_4: U12.4(EN) U13.17(CPEN)

Not connected (* = marked no-connect by the designer): J16 A8(SBU1)* B8(SBU2)*; J17 13(LED1_YELLOW-)* 14(LED1_YELLOW+)*; U13 12(DO_NOT_USE)* 15(SPK_L)* 16(SPK_R)* J1(NC) J9(NC) L1(NC) L9(NC) M7(NC) T7(NC); U14 24(VCONN_FAULT_N)*; U15 7(NC)*; U16 43(LDO_O)* J1(NC) J9(NC) L1(NC) L9(NC) M7(NC) T7(NC)

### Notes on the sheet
- USB VBUS Distribution Switch
- 1.5A max
- USB 2.0 Transceiver
- USB Type C Connector
- USB SuperSpeed MUX
- and Configuration Controller
- Current mode = 1.5 A advertised
- I2C Addr: 1100111
- Ethernet MAC ID PROM
- Ethernet Transceiver
- I2C Addr: 1010111
- Ethernet RJ45
- (near R104) LED Level Shifters
- Title
- Size:
- Date:
- File:
- C
- Number:
- Time:
- Revision:
- Sheet
- of

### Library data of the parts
C69 = 001258: Ceramic Capacitor; Manufacturer: Taiyo Yuden; partnumber: 001258; ValueFloat: 0.00022; x_tolerance: 20
C70-C72 C74 C82-C84 C88-C94 C97-C100 C104-C109 = 000070: Ceramic capacitor; Manufacturer: Kemet; partnumber: 000070; ValueFloat: 1E-7; x_tolerance: 10
C73 = 000752: Ceramic Capacitor; Manufacturer: Taiyo Yuden; partnumber: 000752; ValueFloat: 2.2E-6; x_tolerance: 20
C75 C76 C79-C81 C174 C175 = 000070: Partnumber: 000070; manufacturer: Kemet; ValueFloat: 1E-7; x_tolerance: 10
C77 C78 = 000808: Ceramic capacitor; Manufacturer: Kemet; partnumber: 000808; ValueFloat: 1.2E-11; x_tolerance: 5
C85 C87 C96 C101 C103 = 000824: Ceramic capacitor; Manufacturer: Taiyo Yuden; partnumber: 000824; ValueFloat: 4.7E-6; x_tolerance: 20
C86 C95 C102 = 000824: Partnumber: 000824; manufacturer: Taiyo Yuden; ValueFloat: 4.7E-6; x_tolerance: 20
C110 C111 = 001640: Ceramic capacitor; Manufacturer: Kemet; partnumber: 001640; ValueFloat: 1.8E-11; x_tolerance: 5; x_voltage-rating: 50
C112 = 000491: Ceramic capacitor; Manufacturer: Taiyo Yuden; partnumber: 000491; ValueFloat: 1E-5; x_tolerance: 10
D1 = 001432: LED; Manufacturer: Dialight; Manufacturer_PN: 598-8010-107F; partnumber: 001432
D2 D3 = 001302: Default Diode; Manufacturer: Micro Commercial Co; PartNumber: 001302; manufacturer_pn: 1N4148W-TP; Class I: Discrete; Class II: Diode - Switching
FB1 = 000783: Ferrite Chip; Manufacturer: Murata; partnumber: 000783
FB2 = 000584: Ferrite Bead; Manufacturer: Steward; partnumber: 000584; ValueFloat: 1000; Value: 1 k
FB3 FB4 = 000100: Ferrite bead; Manufacturer: Steward; partnumber: 000100; ValueFloat: 600; Value: 600
J16 = 001907: Partnumber: 001907; manufacturer: Molex
J17 = 001517: RJ-45; Manufacturer: Bel Fuse, Inc.; partnumber: 001517
R65 = 001162: Partnumber: 001162; manufacturer: Vishay; ValueFloat: 2000; x_tolerance: 1
R66 = 001121: Partnumber: 001121; manufacturer: Vishay; ValueFloat: 15000; x_tolerance: 1
R67 R70 R73 R77-R79 R117 = 000755: Thick-film resistor; Manufacturer: Vishay; partnumber: 000755; x_tolerance: 1
R68 R74 R80 R81 R83-R89 R104 R110-R112 R119 = 001521: Thick-film resistor; Manufacturer: Vishay; partnumber: 001521; ValueFloat: 10000; x_tolerance: 1
R69 R115 R116 = 000797: Thick-film resistor; Manufacturer: Vishay; partnumber: 000797; ValueFloat: 1000; x_tolerance: 1
R71 = 001945: Partnumber: 001945; manufacturer: Vishay; ValueFloat: 499000; x_tolerance: 1
R72 = 001853: Partnumber: 001853; manufacturer: Vishay; ValueFloat: 887000; x_tolerance: 1
R75 R113 = 000800: Thick-film resistor; Manufacturer: Vishay; partnumber: 000800; ValueFloat: 1000000; x_tolerance: 5
R76 = 001266: Thick-film resistor; Manufacturer: Vishay; partnumber: 001266; ValueFloat: 8060; x_tolerance: 1
R82 = 001549: Partnumber: 001549; manufacturer: Vishay; ValueFloat: 210000; x_tolerance: 1
R90-R95 R98-R103 R108 R114 = 001008: Thick-film resistor; Manufacturer: Vishay; partnumber: 001008; ValueFloat: 4750; x_tolerance: 1
R96 R97 = 000760: Thick-film resistor; Manufacturer: Vishay; partnumber: 000760; x_tolerance: 1
R105-R107 R118 = 001388: Thick-film resistor; Manufacturer: Vishay; partnumber: 001388; ValueFloat: 2490; x_tolerance: 1
R109 = 001530: Thick-film resistor; Manufacturer: Vishay; partnumber: 001530; ValueFloat: 12100; x_tolerance: 1
U12 = 001278: Adjustable current-limited power switch; Manufacturer: Texas Instruments; partnumber: 001278
U13 = 001262: Hi-Speed USB PHY with ULPI interface; Manufacturer: Microchip; partnumber: 001262
U14 = 001944: Partnumber: 001944; manufacturer: Texas Instruments
U15 = 001296: 2 kb I2C EEPROM, 400 kHz; Manufacturer: Microchip; partnumber: 001296
U16 = 001518: Gigabit ethernet transceiver, RGMII; Manufacturer: Micrel; partnumber: 001518
U17 U18 = 000600: Small Signal MOSFET Dual N-Channel; Manufacturer: Fairchild Semiconductor; partnumber: 000600; PackageDocument: 1995/1996
Y3 = 000770: Crystal; Manufacturer: MMD Monitor / Quartztek; partnumber: 000770
Y4 = 001531: Crystal; Manufacturer: Abracon; partnumber: 001531

## Sheet QSFP.SchDoc: BRK1900 - QSFP
size C; Organization: Opal Kelly; Address1: 13500 SW 72nd Ave STE 100; Address3: Portland, OR  97223; Address4: http://www.opalkelly.com; DocumentNumber: xxx; Revision: 1; SheetNumber: 7; SheetTotal: 9; PageSetup: Record=PageOptions¦CenterHorizontal=True¦CenterVertical=True¦PrintScale=0.52¦XCorrection=1.00¦YCorrection=1.00¦PrintKind=0¦BorderSize=5000000¦LeftOffset=0¦BottomOffset=0¦Orientation=2¦PaperLength=1000¦PaperWidth=1000¦Scale=100¦PaperSource=7¦PrintQuality=-4¦MediaType=1¦DitherType=10¦PaperKind=Letter¦PrintScaleMode=1
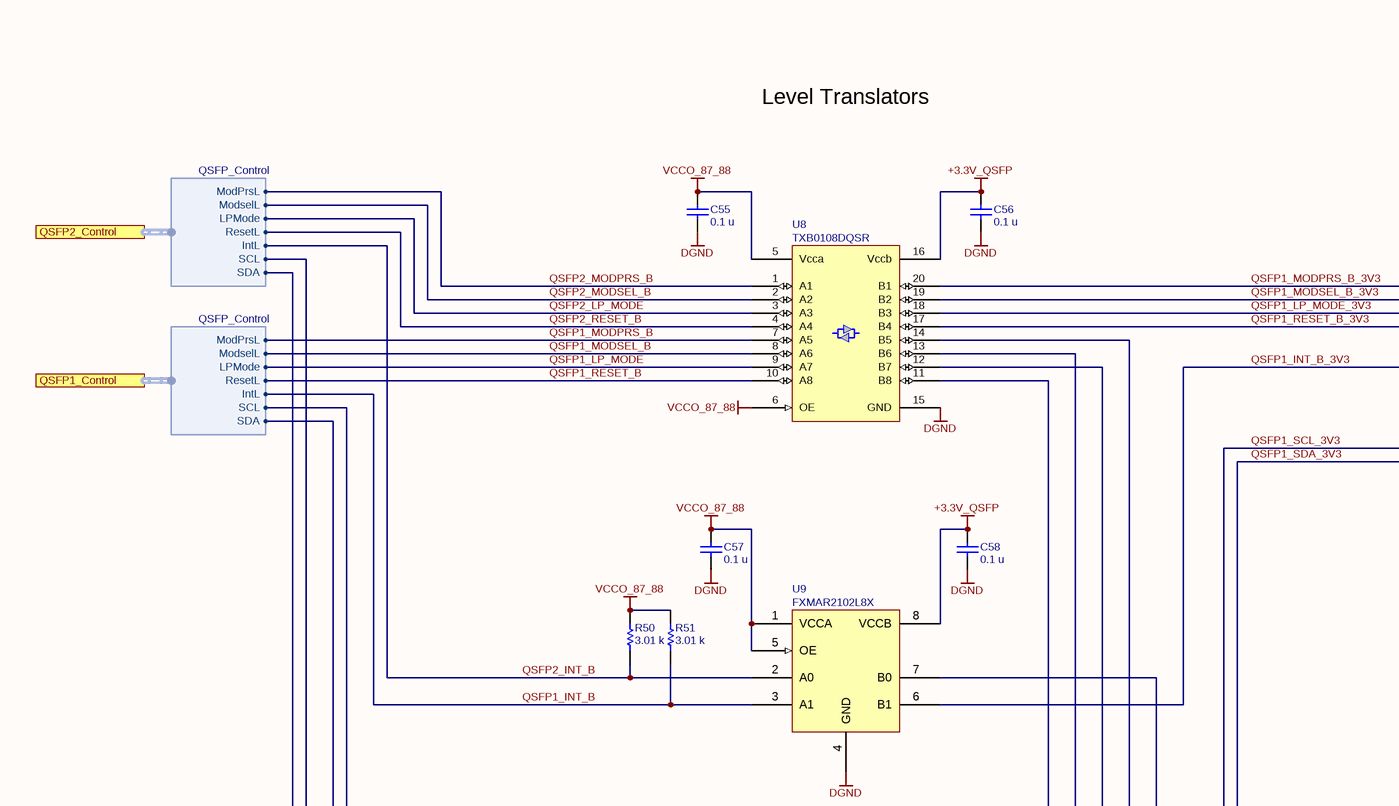
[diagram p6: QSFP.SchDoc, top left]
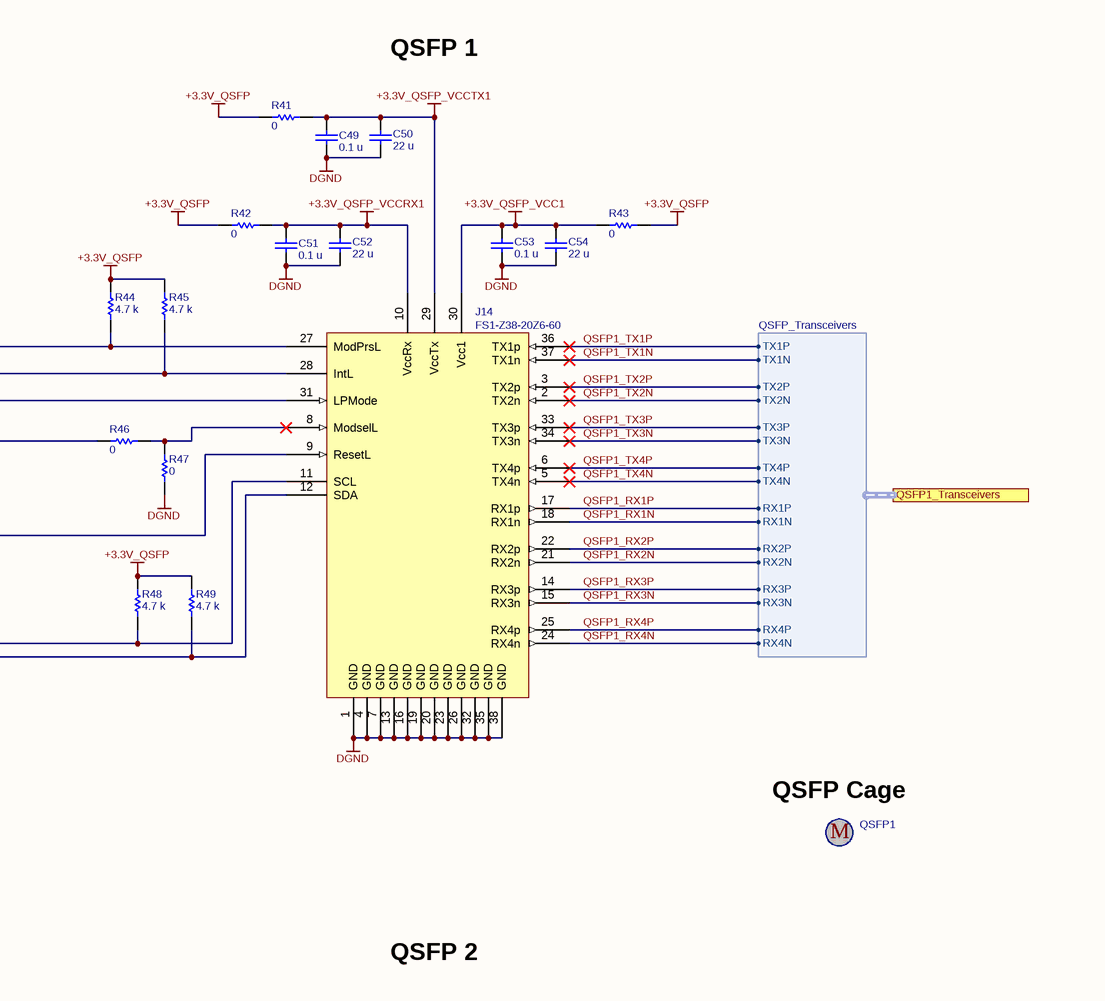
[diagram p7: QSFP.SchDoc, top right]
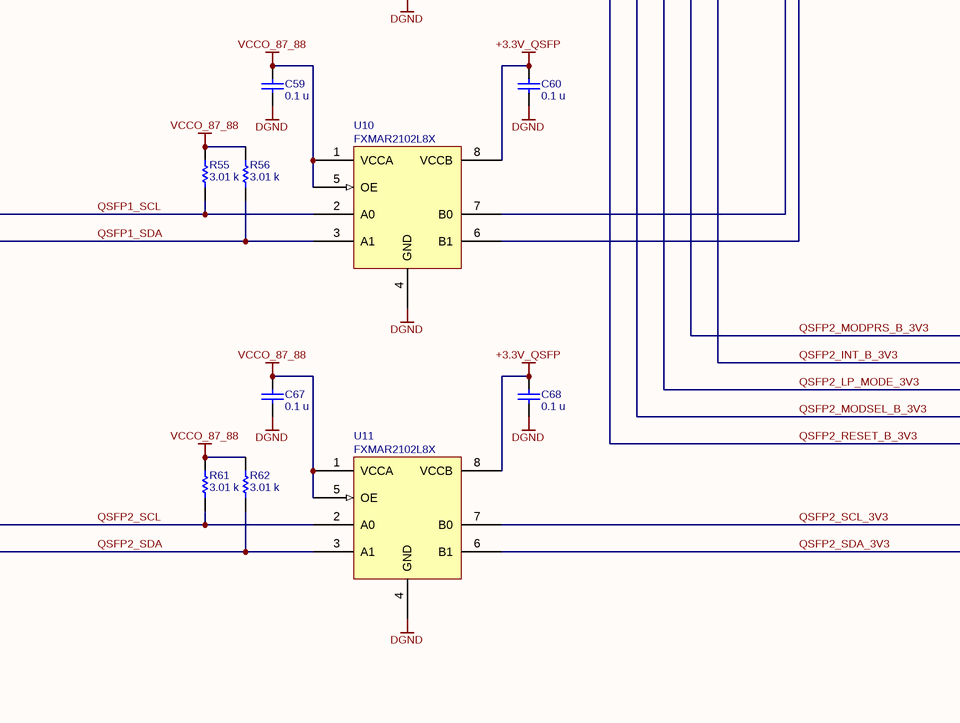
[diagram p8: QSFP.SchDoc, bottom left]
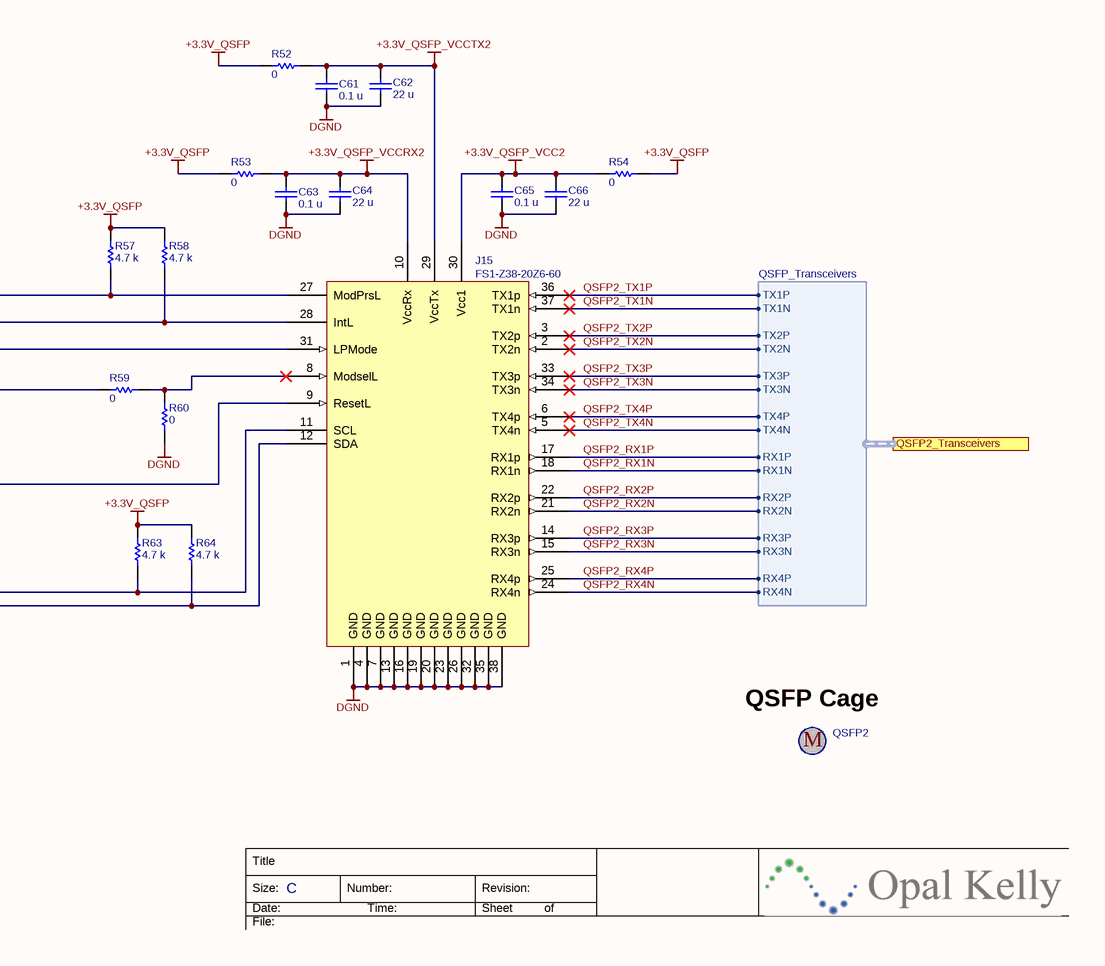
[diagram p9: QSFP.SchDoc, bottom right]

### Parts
C49  value 0.1 u  [CAPC1005X06A]  (hidden comment: SM-0402, 10%, 10v)
C50  value 22 u  [CAPC2012X14N]  (hidden comment: CL21A226MQQNNNE)
C51  value 0.1 u  [CAPC1005X06A]  (hidden comment: SM-0402, 10%, 10v)
C52  value 22 u  [CAPC2012X14N]  (hidden comment: CL21A226MQQNNNE)
C53  value 0.1 u  [CAPC1005X06A]  (hidden comment: C0402C104K8PACTU)
C54  value 22 u  [CAPC2012X14N]  (hidden comment: CL21A226MQQNNNE)
C55  value 0.1 u  [CAPC1005X06A]  (hidden comment: SM-0402, 10%, 10v)
C56  value 0.1 u  [CAPC1005X06A]  (hidden comment: SM-0402, 10%, 10v)
C57  value 0.1 u  [CAPC1005X06A]  (hidden comment: SM-0402, 10%, 10v)
C58  value 0.1 u  [CAPC1005X06A]  (hidden comment: SM-0402, 10%, 10v)
C59  value 0.1 u  [CAPC1005X06A]  (hidden comment: SM-0402, 10%, 10v)
C60  value 0.1 u  [CAPC1005X06A]  (hidden comment: SM-0402, 10%, 10v)
C61  value 0.1 u  [CAPC1005X06A]  (hidden comment: SM-0402, 10%, 10v)
C62  value 22 u  [CAPC2012X14N]  (hidden comment: CL21A226MQQNNNE)
C63  value 0.1 u  [CAPC1005X06A]  (hidden comment: SM-0402, 10%, 10v)
C64  value 22 u  [CAPC2012X14N]  (hidden comment: CL21A226MQQNNNE)
C65  value 0.1 u  [CAPC1005X06A]  (hidden comment: C0402C104K8PACTU)
C66  value 22 u  [CAPC2012X14N]  (hidden comment: CL21A226MQQNNNE)
C67  value 0.1 u  [CAPC1005X06A]  (hidden comment: SM-0402, 10%, 10v)
C68  value 0.1 u  [CAPC1005X06A]  (hidden comment: SM-0402, 10%, 10v)
J14  FS1-Z38-20Z6-60  [QSFP28_RECEPTACLE_SFF-8679]
J15  FS1-Z38-20Z6-60  [QSFP28_RECEPTACLE_SFF-8679]
QSFP1  U95-T111-1001  [QSFP28_SINGLE_CAGE]  (value not drawn)
QSFP2  U95-T111-1001  [QSFP28_SINGLE_CAGE]  (value not drawn)
R41  value 0  [RESC1608N]  (hidden comment: CRCW06030000Z0EA)
R42  value 0  [RESC1608N]  (hidden comment: CRCW06030000Z0EA)
R43  value 0  [RESC1608N]  (hidden comment: CRCW06030000Z0EA)
R44  value 4.7 k  [RESC1005X06A]  (hidden comment: CRCW04024K70JNED)
R45  value 4.7 k  [RESC1005X06A]  (hidden comment: CRCW04024K70JNED)
R46  value 0  [RESC1005X06A]  (hidden comment: CRCW04020000Z0ED)
R47  value 0  [RESC1005X06A]  (hidden comment: CRCW04020000Z0ED)
R48  value 4.7 k  [RESC1005X06A]  (hidden comment: CRCW04024K70JNED)
R49  value 4.7 k  [RESC1005X06A]  (hidden comment: CRCW04024K70JNED)
R50  value 3.01 k  [RESC1005X06A]  (hidden comment: SM-0402, 1%, 1/16W)
R51  value 3.01 k  [RESC1005X06A]  (hidden comment: SM-0402, 1%, 1/16W)
R52  value 0  [RESC1608N]  (hidden comment: CRCW06030000Z0EA)
R53  value 0  [RESC1608N]  (hidden comment: CRCW06030000Z0EA)
R54  value 0  [RESC1608N]  (hidden comment: CRCW06030000Z0EA)
R55  value 3.01 k  [RESC1005X06A]  (hidden comment: SM-0402, 1%, 1/16W)
R56  value 3.01 k  [RESC1005X06A]  (hidden comment: SM-0402, 1%, 1/16W)
R57  value 4.7 k  [RESC1005X06A]  (hidden comment: CRCW04024K70JNED)
R58  value 4.7 k  [RESC1005X06A]  (hidden comment: CRCW04024K70JNED)
R59  value 0  [RESC1005X06A]  (hidden comment: CRCW04020000Z0ED)
R60  value 0  [RESC1005X06A]  (hidden comment: CRCW04020000Z0ED)
R61  value 3.01 k  [RESC1005X06A]  (hidden comment: SM-0402, 1%, 1/16W)
R62  value 3.01 k  [RESC1005X06A]  (hidden comment: SM-0402, 1%, 1/16W)
R63  value 4.7 k  [RESC1005X06A]  (hidden comment: CRCW04024K70JNED)
R64  value 4.7 k  [RESC1005X06A]  (hidden comment: CRCW04024K70JNED)
U8  TXB0108DQSR  [TXB0108DQSR]
U9  FXMAR2102L8X  [FXMAR2102L8X]
U10  FXMAR2102L8X  [FXMAR2102L8X]
U11  FXMAR2102L8X  [FXMAR2102L8X]

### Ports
QSFP1_Control (harness QSFP_Control), QSFP1_Transceivers (harness QSFP_Transceivers), QSFP2_Control (harness QSFP_Control), QSFP2_Transceivers (harness QSFP_Transceivers)

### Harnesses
QSFP_Transceivers: TX1P, TX1N, TX2P, TX2N, TX3P, TX3N, TX4P, TX4N, RX1P, RX1N, RX2P, RX2N, RX3P, RX3N, RX4P, RX4N
QSFP_Control: ModPrsL, IntL, LPMode, ModselL, ResetL, SCL, SDA

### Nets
+3.3V_QSFP: C56.2 C58.2 C60.2 C68.2 R41.1 R42.1 R43.2 R44.2 R45.2 R48.2 R49.2 R52.1 R53.1 R54.2 R57.2 R58.2 R63.2 R64.2 U8.16(Vccb) U9.8(VCCB) U10.8(VCCB) U11.8(VCCB)
+3.3V_QSFP_VCC1: C53.2 C54.2 J14.30(Vcc1) R43.1
+3.3V_QSFP_VCC2: C65.2 C66.2 J15.30(Vcc1) R54.1
+3.3V_QSFP_VCCRX1: C51.2 C52.2 J14.10(VccRx) R42.2
+3.3V_QSFP_VCCRX2: C63.2 C64.2 J15.10(VccRx) R53.2
+3.3V_QSFP_VCCTX1: C49.2 C50.2 J14.29(VccTx) R41.2
+3.3V_QSFP_VCCTX2: C61.2 C62.2 J15.29(VccTx) R52.2
DGND: C49.1 C50.1 C51.1 C52.1 C53.1 C54.1 C55.1 C56.1 C57.1 C58.1 C59.1 C60.1 C61.1 C62.1 C63.1 C64.1 C65.1 C66.1 C67.1 C68.1 J14.1(GND) J14.4(GND) J14.7(GND) J14.13(GND) J14.16(GND) J14.19(GND) J14.20(GND) J14.23(GND) J14.26(GND) J14.32(GND) J14.35(GND) J14.38(GND) J15.1(GND) J15.4(GND) J15.7(GND) J15.13(GND) J15.16(GND) J15.19(GND) J15.20(GND) J15.23(GND) J15.26(GND) J15.32(GND) J15.35(GND) J15.38(GND) R47.1 R60.1 U8.15(GND) U9.4(GND) U10.4(GND) U11.4(GND)
VCCO_87_88: C55.2 C57.2 C59.2 C67.2 R50.2 R51.2 R55.2 R56.2 R61.2 R62.2 U8.5(Vcca) U8.6(OE) U9.1(VCCA) U9.5(OE) U10.1(VCCA) U10.5(OE) U11.1(VCCA) U11.5(OE)
QSFP1_INT_B: R51.1 U9.3(A1) ; port QSFP1_Control.IntL
QSFP1_INT_B_3V3: J14.28(IntL) R45.1 U9.6(B1)
QSFP1_LP_MODE: U8.9(A7) ; port QSFP1_Control.LPMode
QSFP1_LP_MODE_3V3: J14.31(LPMode) U8.18(B3)
QSFP1_MODPRS_B: U8.7(A5) ; port QSFP1_Control.ModPrsL
QSFP1_MODPRS_B_3V3: J14.27(ModPrsL) R44.1 U8.20(B1)
QSFP1_MODSEL_B: U8.8(A6) ; port QSFP1_Control.ModselL
QSFP1_MODSEL_B_3V3: R46.1 U8.19(B2)
QSFP1_RESET_B: U8.10(A8) ; port QSFP1_Control.ResetL
QSFP1_RESET_B_3V3: J14.9(ResetL) U8.17(B4)
QSFP1_RX1N: J14.18(RX1n) ; port QSFP1_Transceivers.RX1N
QSFP1_RX1P: J14.17(RX1p) ; port QSFP1_Transceivers.RX1P
QSFP1_RX2N: J14.21(RX2n) ; port QSFP1_Transceivers.RX2N
QSFP1_RX2P: J14.22(RX2p) ; port QSFP1_Transceivers.RX2P
QSFP1_RX3N: J14.15(RX3n) ; port QSFP1_Transceivers.RX3N
QSFP1_RX3P: J14.14(RX3p) ; port QSFP1_Transceivers.RX3P
QSFP1_RX4N: J14.24(RX4n) ; port QSFP1_Transceivers.RX4N
QSFP1_RX4P: J14.25(RX4p) ; port QSFP1_Transceivers.RX4P
QSFP1_SCL: R55.1 U10.2(A0) ; port QSFP1_Control.SCL
QSFP1_SCL_3V3: J14.11(SCL) R48.1 U10.7(B0)
QSFP1_SDA: R56.1 U10.3(A1) ; port QSFP1_Control.SDA
QSFP1_SDA_3V3: J14.12(SDA) R49.1 U10.6(B1)
QSFP1_TX1N: J14.37(TX1n) ; port QSFP1_Transceivers.TX1N
QSFP1_TX1P: J14.36(TX1p) ; port QSFP1_Transceivers.TX1P
QSFP1_TX2N: J14.2(TX2n) ; port QSFP1_Transceivers.TX2N
QSFP1_TX2P: J14.3(TX2p) ; port QSFP1_Transceivers.TX2P
QSFP1_TX3N: J14.34(TX3n) ; port QSFP1_Transceivers.TX3N
QSFP1_TX3P: J14.33(TX3p) ; port QSFP1_Transceivers.TX3P
QSFP1_TX4N: J14.5(TX4n) ; port QSFP1_Transceivers.TX4N
QSFP1_TX4P: J14.6(TX4p) ; port QSFP1_Transceivers.TX4P
QSFP2_INT_B: R50.1 U9.2(A0) ; port QSFP2_Control.IntL
QSFP2_INT_B_3V3: J15.28(IntL) R58.1 U9.7(B0)
QSFP2_LP_MODE: U8.3(A3) ; port QSFP2_Control.LPMode
QSFP2_LP_MODE_3V3: J15.31(LPMode) U8.12(B7)
QSFP2_MODPRS_B: U8.1(A1) ; port QSFP2_Control.ModPrsL
QSFP2_MODPRS_B_3V3: J15.27(ModPrsL) R57.1 U8.14(B5)
QSFP2_MODSEL_B: U8.2(A2) ; port QSFP2_Control.ModselL
QSFP2_MODSEL_B_3V3: R59.1 U8.13(B6)
QSFP2_RESET_B: U8.4(A4) ; port QSFP2_Control.ResetL
QSFP2_RESET_B_3V3: J15.9(ResetL) U8.11(B8)
QSFP2_RX1N: J15.18(RX1n) ; port QSFP2_Transceivers.RX1N
QSFP2_RX1P: J15.17(RX1p) ; port QSFP2_Transceivers.RX1P
QSFP2_RX2N: J15.21(RX2n) ; port QSFP2_Transceivers.RX2N
QSFP2_RX2P: J15.22(RX2p) ; port QSFP2_Transceivers.RX2P
QSFP2_RX3N: J15.15(RX3n) ; port QSFP2_Transceivers.RX3N
QSFP2_RX3P: J15.14(RX3p) ; port QSFP2_Transceivers.RX3P
QSFP2_RX4N: J15.24(RX4n) ; port QSFP2_Transceivers.RX4N
QSFP2_RX4P: J15.25(RX4p) ; port QSFP2_Transceivers.RX4P
QSFP2_SCL: R61.1 U11.2(A0) ; port QSFP2_Control.SCL
QSFP2_SCL_3V3: J15.11(SCL) R63.1 U11.7(B0)
QSFP2_SDA: R62.1 U11.3(A1) ; port QSFP2_Control.SDA
QSFP2_SDA_3V3: J15.12(SDA) R64.1 U11.6(B1)
QSFP2_TX1N: J15.37(TX1n) ; port QSFP2_Transceivers.TX1N
QSFP2_TX1P: J15.36(TX1p) ; port QSFP2_Transceivers.TX1P
QSFP2_TX2N: J15.2(TX2n) ; port QSFP2_Transceivers.TX2N
QSFP2_TX2P: J15.3(TX2p) ; port QSFP2_Transceivers.TX2P
QSFP2_TX3N: J15.34(TX3n) ; port QSFP2_Transceivers.TX3N
QSFP2_TX3P: J15.33(TX3p) ; port QSFP2_Transceivers.TX3P
QSFP2_TX4N: J15.5(TX4n) ; port QSFP2_Transceivers.TX4N
QSFP2_TX4P: J15.6(TX4p) ; port QSFP2_Transceivers.TX4P
NetJ14_8: J14.8(ModselL) R46.2 R47.2
NetJ15_8: J15.8(ModselL) R59.2 R60.2

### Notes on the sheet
- QSFP 1
- Level Translators
- (near QSFP1) QSFP Cage
- QSFP 2
- (near QSFP2) QSFP Cage
- Title
- Size:
- Date:
- File:
- C
- Number:
- Time:
- Revision:
- Sheet
- of

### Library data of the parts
C49 C51 C55-C61 C63 C67 C68 = 000070: Partnumber: 000070; manufacturer: Kemet; manufacturer_pn: C0402C104K8PACTU; ValueFloat: 1E-7; id: 750; inventory_price: 0.0023; reorder_quantity: 70000; x_tolerance: 10
C50 C52 C54 C62 C64 C66 = 001792: Partnumber: 001792; manufacturer: Samsung Electro-Mechanics; ValueFloat: 2.2E-5; x_tolerance: 20
C53 C65 = 000070: as C75 on sheet USB_Ethernet
J14 J15 = 001782: QSFP28 38-POS Receptacle; Partnumber: 001782; manufacturer: Amphenol
QSFP1 QSFP2 = 001781: QSFP28 Single Cage; Partnumber: 001781; manufacturer: Amphenol
R41-R43 R52-R54 = 000411: Partnumber: 000411; manufacturer: Vishay
R44 R45 R48 R49 R57 R58 R63 R64 = 000754: Partnumber: 000754; manufacturer: Vishay; ValueFloat: 4700; x_tolerance: 5
R46 R47 R59 R60 = 000755: Partnumber: 000755; manufacturer: Vishay; x_tolerance: 1
R50 R51 R55 R56 R61 R62 = 001126: Partnumber: 001126; manufacturer: Vishay; manufacturer_pn: CRCW04023K01FKED; ValueFloat: 3010; id: 35682; inventory_price: 0.015; x_tolerance: 1
U8 = 001324: Partnumber: 001324; manufacturer: Texas Instruments; id: 94563; inventory_price: 1.67
U9-U11 = 001559: Partnumber: 001559; manufacturer: ON Semiconductor; id: 168047; inventory_price: 0.3

## Sheet Expansion-MC1.SchDoc: BRK1900 - Expansion MC1
size C; Organization: Opal Kelly; Address1: 13500 SW 72nd Ave STE 100; Address3: Portland, OR  97223; Address4: http://www.opalkelly.com; DocumentNumber: xxx; Revision: 1; SheetNumber: 2; SheetTotal: 9; PageSetup: Record=PageOptions¦CenterHorizontal=True¦CenterVertical=True¦PrintScale=0.52¦XCorrection=1.00¦YCorrection=1.00¦PrintKind=0¦BorderSize=5000000¦LeftOffset=0¦BottomOffset=0¦Orientation=2¦PaperLength=1000¦PaperWidth=1000¦Scale=100¦PaperSource=7¦PrintQuality=-4¦MediaType=1¦DitherType=10¦PaperKind=Letter¦PrintScaleMode=1
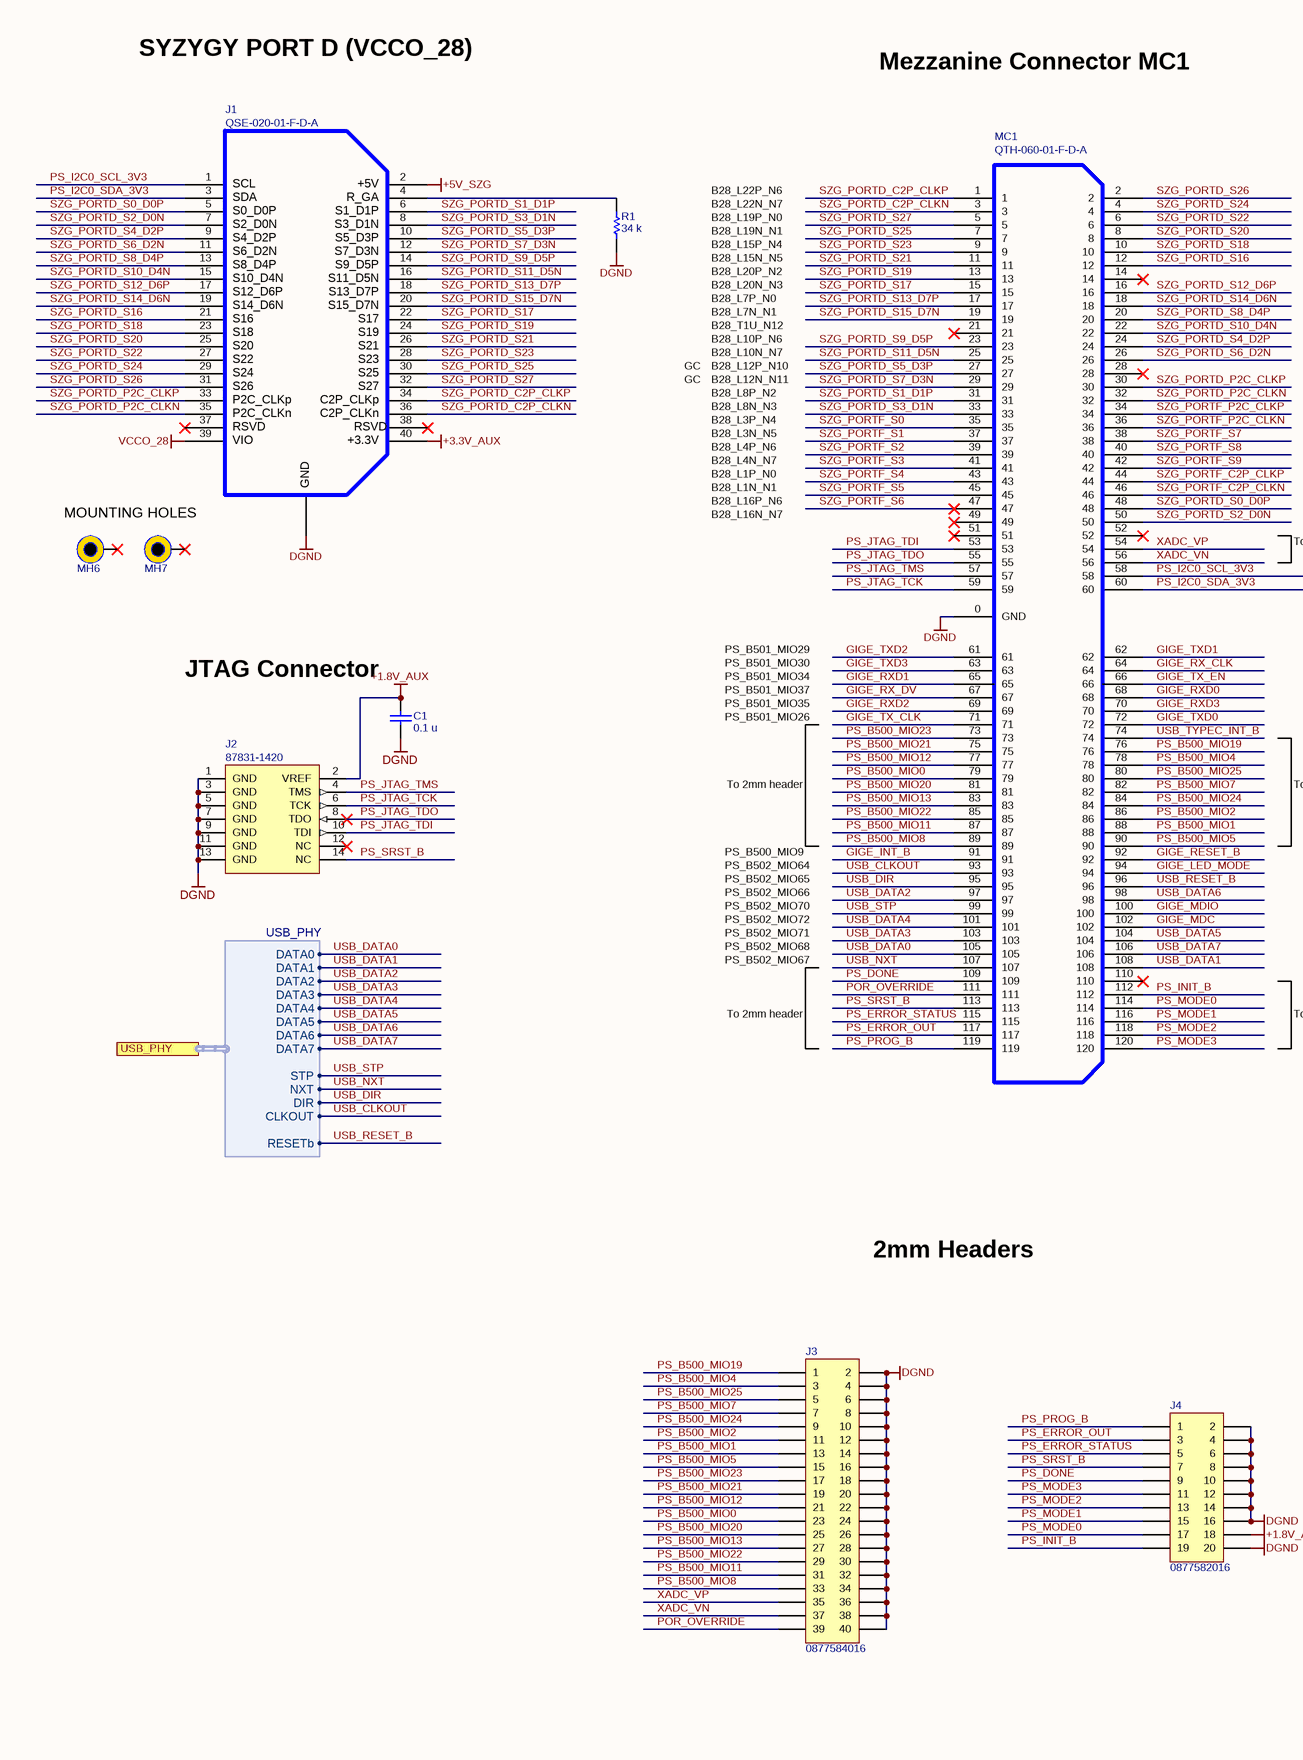
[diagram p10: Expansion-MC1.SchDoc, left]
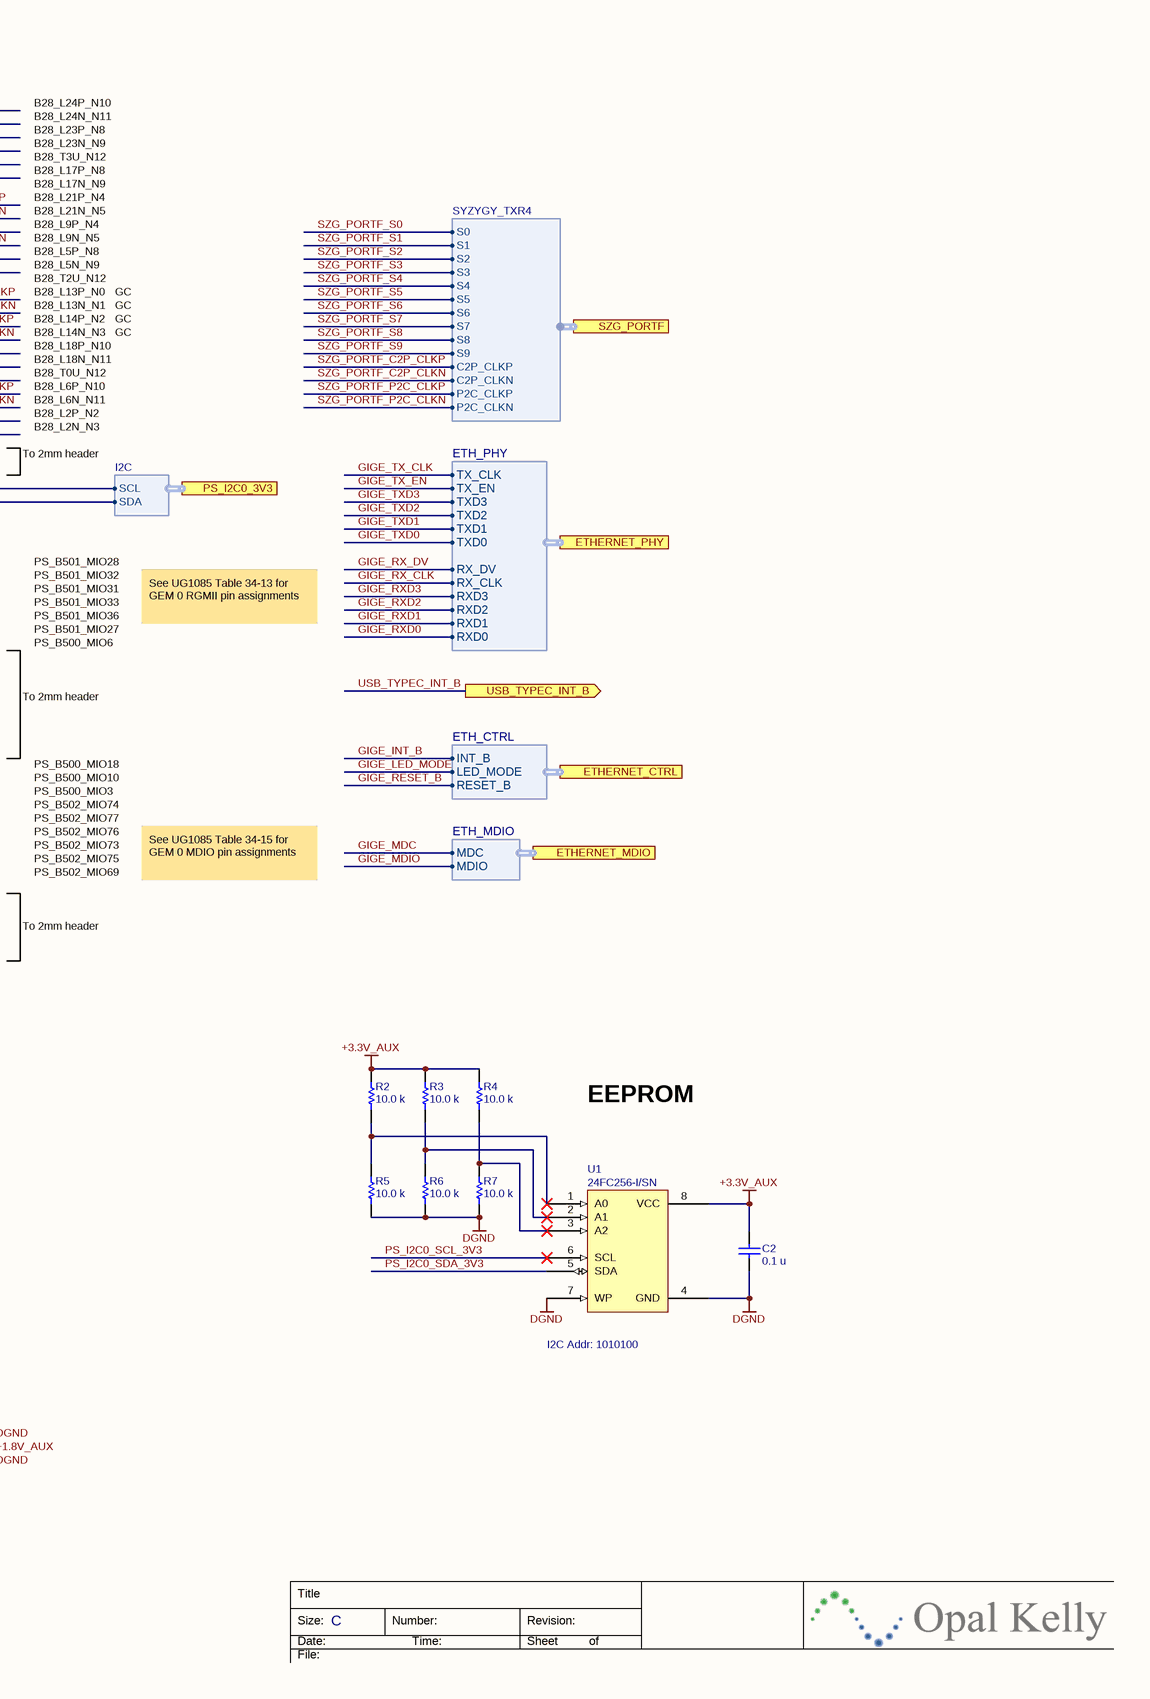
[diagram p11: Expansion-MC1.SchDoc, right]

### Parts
C1  value 0.1 u  [CAPC1005X06A]  (hidden comment: C0402C104K8PACTU)
C2  value 0.1 u  [CAPC1005X06A]  (hidden comment: C0402C104K8PACTU)
J1  QSE-020-01-F-D-A  [QSE-020-01-X-D-A-L]
J2  87831-1420  [HDR2X7-2MM]
J3  0877584016  [HDR2X20-2MM]
J4  0877582016  [HDR2X10-2MM]
MC1  QTH-060-01-F-D-A  [QTH-060-01-X-D]
MH6  MTG  [MTG-2.7/5.0-PTH]  (value not drawn)
MH7  MTG  [MTG-2.7/5.0-PTH]  (value not drawn)
R1  value 34 k  [RESC1005X06A]  (hidden comment: CRCW040234K0FKED)
R2  value 10.0 k  [RESC1005X06A]  (hidden comment: CRCW040210K0FKED)
R3  value 10.0 k  [RESC1005X06A]  (hidden comment: CRCW040210K0FKED)
R4  value 10.0 k  [RESC1005X06A]  (hidden comment: CRCW040210K0FKED)
R5  value 10.0 k  [RESC1005X06A]  (hidden comment: CRCW040210K0FKED)
R6  value 10.0 k  [RESC1005X06A]  (hidden comment: CRCW040210K0FKED)
R7  value 10.0 k  [RESC1005X06A]  (hidden comment: CRCW040210K0FKED)
U1  24FC256-I/SN  [SO-G8]

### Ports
ETHERNET_CTRL (harness ETH_CTRL), ETHERNET_MDIO (harness ETH_MDIO), ETHERNET_PHY (harness ETH_PHY), PS_I2C0_3V3 (harness I2C), SZG_PORTF (harness SYZYGY_TXR4), USB_PHY (harness USB_PHY), USB_TYPEC_INT_B (out)

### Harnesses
I2C: SCL, SDA
SYZYGY_TXR4: S0, S1, S2, S3, S4, S5, S6, S7, S8, S9, C2P_CLKP, C2P_CLKN, P2C_CLKP, P2C_CLKN
ETH_PHY: TX_CLK, TX_EN, TXD3, TXD2, TXD1, TXD0, RX_DV, RX_CLK, RXD3, RXD2, RXD1, RXD0
ETH_CTRL: INT_B, LED_MODE, RESET_B
ETH_MDIO: MDC, MDIO
USB_PHY: DATA0, DATA1, DATA2, DATA3, DATA4, DATA5, DATA6, DATA7, STP, NXT, DIR, CLKOUT, RESETb

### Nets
+1.8V_AUX: C1.2 J2.2(VREF) J4.18
+3.3V_AUX: C2.2 J1.40 R2.2 R3.2 R4.2 U1.8(VCC)
+5V_SZG: J1.2
DGND: C1.1 C2.1 J1.0 J2.1(GND) J2.3(GND) J2.5(GND) J2.7(GND) J2.9(GND) J2.11(GND) J2.13(GND) J3.2 J3.4 J3.6 J3.8 J3.10 J3.12 J3.14 J3.16 J3.18 J3.20 J3.22 J3.24 J3.26 J3.28 J3.30 J3.32 J3.34 J3.36 J3.38 J3.40 J4.2 J4.4 J4.6 J4.8 J4.10 J4.12 J4.14 J4.16 J4.20 MC1.0(GND) R1.1 R5.1 R6.1 R7.1 U1.4(GND) U1.7(WP)
VCCO_28: J1.39
GIGE_INT_B: MC1.91 ; port ETHERNET_CTRL.INT_B
GIGE_LED_MODE: MC1.94 ; port ETHERNET_CTRL.LED_MODE
GIGE_MDC: MC1.102 ; port ETHERNET_MDIO.MDC
GIGE_MDIO: MC1.100 ; port ETHERNET_MDIO.MDIO
GIGE_RESET_B: MC1.92 ; port ETHERNET_CTRL.RESET_B
GIGE_RX_CLK: MC1.64 ; port ETHERNET_PHY.RX_CLK
GIGE_RX_DV: MC1.67 ; port ETHERNET_PHY.RX_DV
GIGE_RXD0: MC1.68 ; port ETHERNET_PHY.RXD0
GIGE_RXD1: MC1.65 ; port ETHERNET_PHY.RXD1
GIGE_RXD2: MC1.69 ; port ETHERNET_PHY.RXD2
GIGE_RXD3: MC1.70 ; port ETHERNET_PHY.RXD3
GIGE_TX_CLK: MC1.71 ; port ETHERNET_PHY.TX_CLK
GIGE_TX_EN: MC1.66 ; port ETHERNET_PHY.TX_EN
GIGE_TXD0: MC1.72 ; port ETHERNET_PHY.TXD0
GIGE_TXD1: MC1.62 ; port ETHERNET_PHY.TXD1
GIGE_TXD2: MC1.61 ; port ETHERNET_PHY.TXD2
GIGE_TXD3: MC1.63 ; port ETHERNET_PHY.TXD3
POR_OVERRIDE: J3.39 MC1.111
PS_B500_MIO0: J3.23 MC1.79
PS_B500_MIO1: J3.13 MC1.88
PS_B500_MIO2: J3.11 MC1.86
PS_B500_MIO4: J3.3 MC1.78
PS_B500_MIO5: J3.15 MC1.90
PS_B500_MIO7: J3.7 MC1.82
PS_B500_MIO8: J3.33 MC1.89
PS_B500_MIO11: J3.31 MC1.87
PS_B500_MIO12: J3.21 MC1.77
PS_B500_MIO13: J3.27 MC1.83
PS_B500_MIO19: J3.1 MC1.76
PS_B500_MIO20: J3.25 MC1.81
PS_B500_MIO21: J3.19 MC1.75
PS_B500_MIO22: J3.29 MC1.85
PS_B500_MIO23: J3.17 MC1.73
PS_B500_MIO24: J3.9 MC1.84
PS_B500_MIO25: J3.5 MC1.80
PS_DONE: J4.9 MC1.109
PS_ERROR_OUT: J4.3 MC1.117
PS_ERROR_STATUS: J4.5 MC1.115
PS_I2C0_SCL_3V3: J1.1 MC1.58 U1.6(SCL) ; port PS_I2C0_3V3.SCL
PS_I2C0_SDA_3V3: J1.3 MC1.60 U1.5(SDA) ; port PS_I2C0_3V3.SDA
PS_INIT_B: J4.19 MC1.112
PS_JTAG_TCK: J2.6(TCK) MC1.59
PS_JTAG_TDI: J2.10(TDI) MC1.53
PS_JTAG_TDO: J2.8(TDO) MC1.55
PS_JTAG_TMS: J2.4(TMS) MC1.57
PS_MODE0: J4.17 MC1.114
PS_MODE1: J4.15 MC1.116
PS_MODE2: J4.13 MC1.118
PS_MODE3: J4.11 MC1.120
PS_PROG_B: J4.1 MC1.119
PS_SRST_B: J2.14(NC) J4.7 MC1.113
SZG_PORTD_C2P_CLKN: J1.36 MC1.3
SZG_PORTD_C2P_CLKP: J1.34 MC1.1
SZG_PORTD_P2C_CLKN: J1.35 MC1.32
SZG_PORTD_P2C_CLKP: J1.33 MC1.30
SZG_PORTD_S0_D0P: J1.5 MC1.48
SZG_PORTD_S1_D1P: J1.6 MC1.31
SZG_PORTD_S2_D0N: J1.7 MC1.50
SZG_PORTD_S3_D1N: J1.8 MC1.33
SZG_PORTD_S4_D2P: J1.9 MC1.24
SZG_PORTD_S5_D3P: J1.10 MC1.27
SZG_PORTD_S6_D2N: J1.11 MC1.26
SZG_PORTD_S7_D3N: J1.12 MC1.29
SZG_PORTD_S8_D4P: J1.13 MC1.20
SZG_PORTD_S9_D5P: J1.14 MC1.23
SZG_PORTD_S10_D4N: J1.15 MC1.22
SZG_PORTD_S11_D5N: J1.16 MC1.25
SZG_PORTD_S12_D6P: J1.17 MC1.16
SZG_PORTD_S13_D7P: J1.18 MC1.17
SZG_PORTD_S14_D6N: J1.19 MC1.18
SZG_PORTD_S15_D7N: J1.20 MC1.19
SZG_PORTD_S16: J1.21 MC1.12
SZG_PORTD_S17: J1.22 MC1.15
SZG_PORTD_S18: J1.23 MC1.10
SZG_PORTD_S19: J1.24 MC1.13
SZG_PORTD_S20: J1.25 MC1.8
SZG_PORTD_S21: J1.26 MC1.11
SZG_PORTD_S22: J1.27 MC1.6
SZG_PORTD_S23: J1.28 MC1.9
SZG_PORTD_S24: J1.29 MC1.4
SZG_PORTD_S25: J1.30 MC1.7
SZG_PORTD_S26: J1.31 MC1.2
SZG_PORTD_S27: J1.32 MC1.5
SZG_PORTF_C2P_CLKN: MC1.46 ; port SZG_PORTF.C2P_CLKN
SZG_PORTF_C2P_CLKP: MC1.44 ; port SZG_PORTF.C2P_CLKP
SZG_PORTF_P2C_CLKN: MC1.36 ; port SZG_PORTF.P2C_CLKN
SZG_PORTF_P2C_CLKP: MC1.34 ; port SZG_PORTF.P2C_CLKP
SZG_PORTF_S0: MC1.35 ; port SZG_PORTF.S0
SZG_PORTF_S1: MC1.37 ; port SZG_PORTF.S1
SZG_PORTF_S2: MC1.39 ; port SZG_PORTF.S2
SZG_PORTF_S3: MC1.41 ; port SZG_PORTF.S3
SZG_PORTF_S4: MC1.43 ; port SZG_PORTF.S4
SZG_PORTF_S5: MC1.45 ; port SZG_PORTF.S5
SZG_PORTF_S6: MC1.47 ; port SZG_PORTF.S6
SZG_PORTF_S7: MC1.38 ; port SZG_PORTF.S7
SZG_PORTF_S8: MC1.40 ; port SZG_PORTF.S8
SZG_PORTF_S9: MC1.42 ; port SZG_PORTF.S9
USB_CLKOUT: MC1.93 ; port USB_PHY.CLKOUT
USB_DATA0: MC1.105 ; port USB_PHY.DATA0
USB_DATA1: MC1.108 ; port USB_PHY.DATA1
USB_DATA2: MC1.97 ; port USB_PHY.DATA2
USB_DATA3: MC1.103 ; port USB_PHY.DATA3
USB_DATA4: MC1.101 ; port USB_PHY.DATA4
USB_DATA5: MC1.104 ; port USB_PHY.DATA5
USB_DATA6: MC1.98 ; port USB_PHY.DATA6
USB_DATA7: MC1.106 ; port USB_PHY.DATA7
USB_DIR: MC1.95 ; port USB_PHY.DIR
USB_NXT: MC1.107 ; port USB_PHY.NXT
USB_RESET_B: MC1.96 ; port USB_PHY.RESETb
USB_STP: MC1.99 ; port USB_PHY.STP
USB_TYPEC_INT_B: MC1.74 ; port USB_TYPEC_INT_B
XADC_VN: J3.37 MC1.56
XADC_VP: J3.35 MC1.54
NetJ1_4: J1.4 R1.2
NetR2_1: R2.1 R5.2 U1.1(A0)
NetR3_1: R3.1 R6.2 U1.2(A1)
NetR4_1: R4.1 R7.2 U1.3(A2)

Not connected (* = marked no-connect by the designer): J1 37* 38*; J2 12(NC)*; MC1 14* 21* 28* 49* 51* 52* 110*; MH6 1*; MH7 1*

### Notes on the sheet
- SYZYGY PORT D (VCCO_28)
- Mezzanine Connector MC1
- B28_L22P_N6
- B28_L24P_N10
- B28_L22N_N7
- B28_L19P_N0
- B28_L19N_N1
- B28_L15P_N4
- B28_L15N_N5
- B28_L24N_N11
- B28_L23P_N8
- B28_L23N_N9
- B28_T3U_N12
- B28_L17P_N8
- B28_L20P_N2
- B28_L20N_N3
- B28_L7P_N0
- B28_L7N_N1
- B28_T1U_N12
- B28_L17N_N9
- B28_L21P_N4
- B28_L21N_N5
- B28_L9P_N4
- B28_L9N_N5
- GC
- B28_L10P_N6
- B28_L10N_N7
- B28_L12P_N10
- B28_L12N_N11
- B28_L8P_N2
- B28_L5P_N8
- B28_L5N_N9
- B28_T2U_N12
- B28_L13P_N0
- B28_L13N_N1
- B28_L8N_N3
- B28_L3P_N4
- B28_L3N_N5
- B28_L4P_N6
- B28_L4N_N7
- B28_L14P_N2
- B28_L14N_N3
- B28_L18P_N10
- B28_L18N_N11
- B28_T0U_N12
- MOUNTING HOLES
- B28_L1P_N0
- B28_L1N_N1
- B28_L16P_N6
- B28_L16N_N7
- B28_L6P_N10
- B28_L6N_N11
- B28_L2P_N2
- B28_L2N_N3
- To 2mm header
- PS_B501_MIO29
- PS_B501_MIO30
- PS_B501_MIO28
- PS_B501_MIO32
- (near C1) JTAG Connector
- PS_B501_MIO34
- PS_B501_MIO37
- PS_B501_MIO35
- PS_B501_MIO26
- PS_B501_MIO31
- PS_B501_MIO33
- PS_B501_MIO36
- PS_B501_MIO27
- PS_B500_MIO6
- See UG1085 Table 34-13 for GEM 0 RGMII pin assignments
- PS_B500_MIO9
- PS_B502_MIO64
- PS_B500_MIO18
- PS_B500_MIO10
- PS_B502_MIO66
- PS_B502_MIO70
- PS_B502_MIO72
- PS_B502_MIO71
- PS_B502_MIO65
- PS_B502_MIO74
- PS_B502_MIO77
- PS_B502_MIO76
- PS_B502_MIO73
- PS_B500_MIO3
- PS_B502_MIO68
- PS_B502_MIO67
- PS_B502_MIO75
- PS_B502_MIO69
- See UG1085 Table 34-15 for GEM 0 MDIO pin assignments
- EEPROM
- 2mm Headers
- (near U1) I2C Addr: 1010100
- Title
- Size:
- Date:
- File:
- C
- Number:
- Time:
- Revision:
- Sheet
- of

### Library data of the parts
C1 C2 = 000070: Ceramic capacitor; Partnumber: 000070; manufacturer: Kemet; ValueFloat: 1E-7; x_tolerance: 10
J1 = 001604: 0.8mm hi-speed, high-density header (male); Manufacturer: Samtec; partnumber: 001604
J2 = 000541: 2mm header, shrouded; Manufacturer: Molex; partnumber: 000541
J3 = 000583: Partnumber: 000583; manufacturer: Molex
J4 = 001338: Partnumber: 001338; manufacturer: Molex
MC1 = 000855: 0.5mm Double Row High Speed Socket Assembly; Manufacturer: Samtec; partnumber: 000855; Description 2: 180 Pins - HSMC Host Compatible - 9GHz
MH6 MH7 = MTG: Mounting hole; partnumber: ALIGNI_IGNORE
R1 = 001551: Partnumber: 001551; manufacturer: Vishay; ValueFloat: 34000; x_tolerance: 1
R2-R7 = 001521: Thick-film resistor; Partnumber: 001521; manufacturer: Vishay; ValueFloat: 10000; x_tolerance: 1
U1 = 000842: EEPROM; Partnumber: 000842; manufacturer: Microchip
